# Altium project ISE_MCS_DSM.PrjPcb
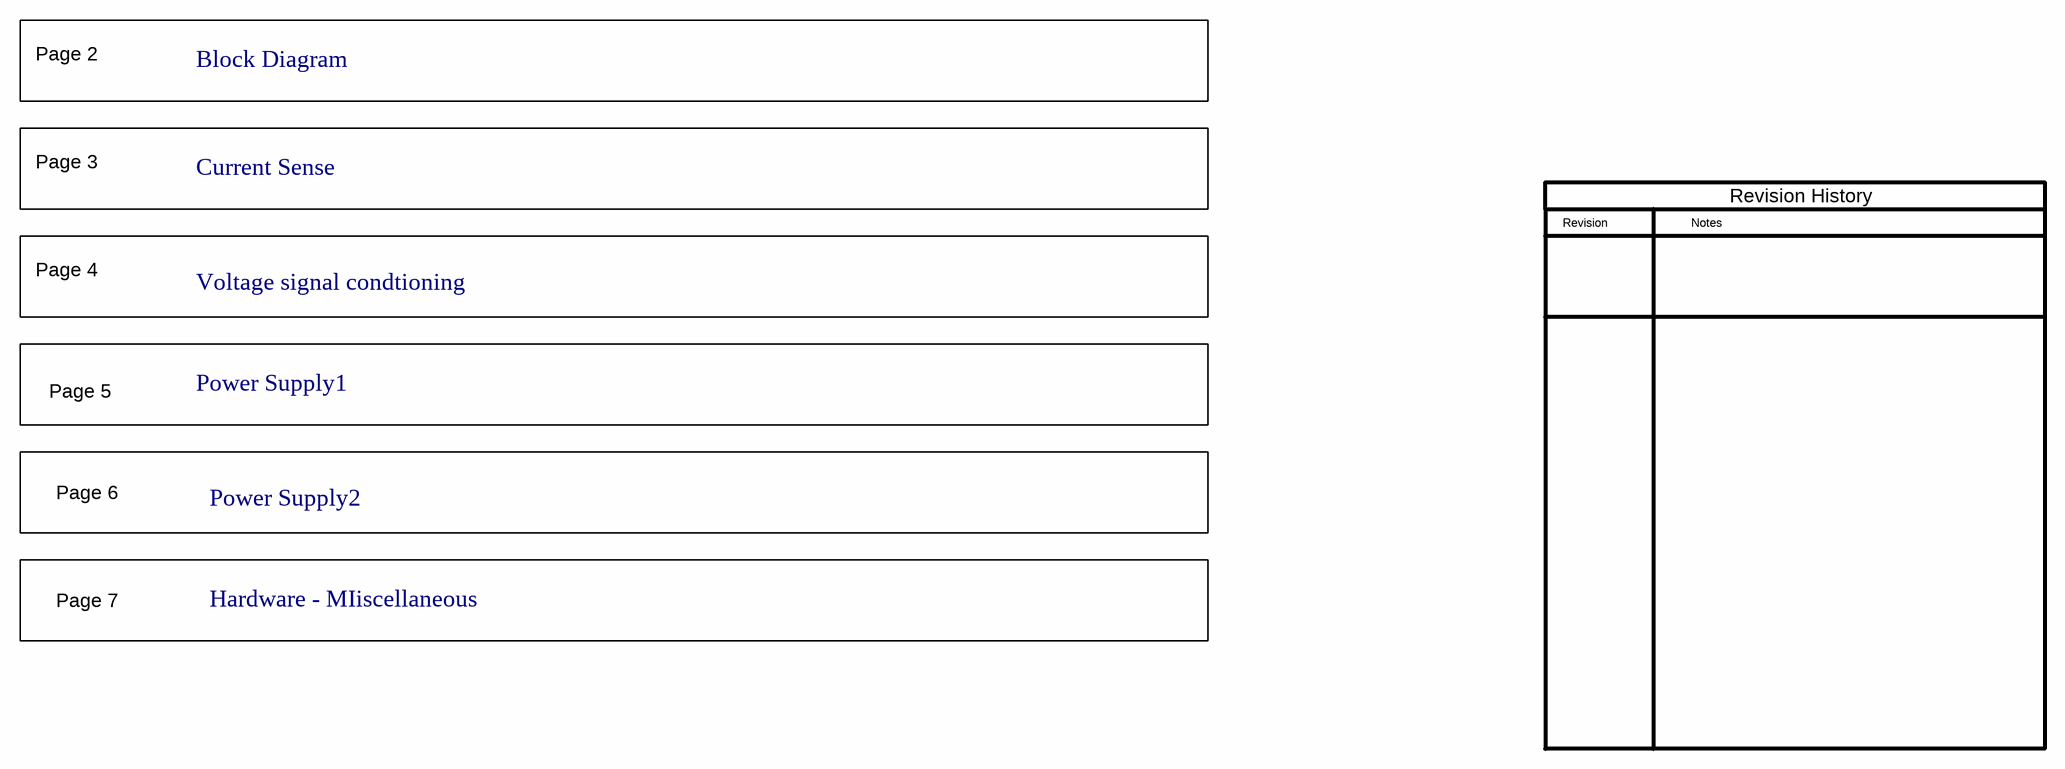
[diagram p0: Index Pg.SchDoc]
CopyrightYear: 2014; PCB_Layout: Vamsi T; PCB_Rev: E2; PRJ_Customer: Public Release; PRJ_Engineer: Narayanasamy Navaneeth; PRJ_Number: TIDA-00171; PRJ_Title: ISE_MCS_DSM_E2; SCH_Rev: E2; TechSupport: http://www.ti.com/support
7 sheets, 401 parts. Net scope: flat (ports and power ports of the same name join across sheets).
Board file: ISE_MCS_DSM_E2.PcbDoc
Sheets:
  Index Pg.SchDoc
  Block Diagram.SchDoc
  Current Sense.SchDoc
  Voltage signal conditioning.SchDoc
  Power supply 1.SchDoc
  Power supply 2.SchDoc
  Hardware.SchDoc

## Sheet Index Pg.SchDoc: Index Page
size 431 x 279 mm; Date: Not shown in title block; ApprovedBy: Not shown in title block; CheckedBy: Not shown in title block; Author: Not shown in title block; CompanyName: Not shown in title block; Engineer: Not shown in title block; Organization: Not shown in title block; Address1: Not shown in title block; Address2: Not shown in title block; Address3: Not shown in title block; Address4: Not shown in title block; DocumentNumber: 1; Revision: Use project parameter SCH_Rev; SheetNumber: 1; SheetTotal: 7; PageSetup: Record=PageOptions|CenterHorizontal=True|CenterVertical=True|PrintScale=1.00|XCorrection=1.00|YCorrection=1.00|PrintKind=0|BorderSize=5000000|LeftOffset=0|BottomOffset=0|Orientation=2|PaperLength=1000|PaperWidth=1000|Scale=100|PaperSource=15|PrintQuality=600|MediaType=1|DitherType=10|PaperKind=Letter|PrintScaleMode=1

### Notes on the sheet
- Page 2
- Block Diagram
- Page 3
- Current Sense
- Revision History
- Page 4
- Revision
- Notes
- Voltage signal condtioning
- Page 5
- Power Supply1
- Page 6
- Power Supply2
- Page 7
- Hardware - MIiscellaneous

## Sheet Block Diagram.SchDoc: Block Diagram
size 431 x 279 mm; Date: Not shown in title block; ApprovedBy: Not shown in title block; CheckedBy: Not shown in title block; Author: Not shown in title block; CompanyName: Not shown in title block; Engineer: Not shown in title block; Organization: Not shown in title block; Address1: Not shown in title block; Address2: Not shown in title block; Address3: Not shown in title block; Address4: Not shown in title block; DocumentNumber: 2; Revision: Use project parameter SCH_Rev; SheetNumber: 2; SheetTotal: 7; PageSetup: Record=PageOptions|CenterHorizontal=True|CenterVertical=True|PrintScale=1.00|XCorrection=1.00|YCorrection=1.00|PrintKind=0|BorderSize=5000000|LeftOffset=0|BottomOffset=0|Orientation=2|PaperLength=1000|PaperWidth=1000|Scale=100|PaperSource=15|PrintQuality=600|MediaType=1|DitherType=10|PaperKind=Letter|PrintScaleMode=1
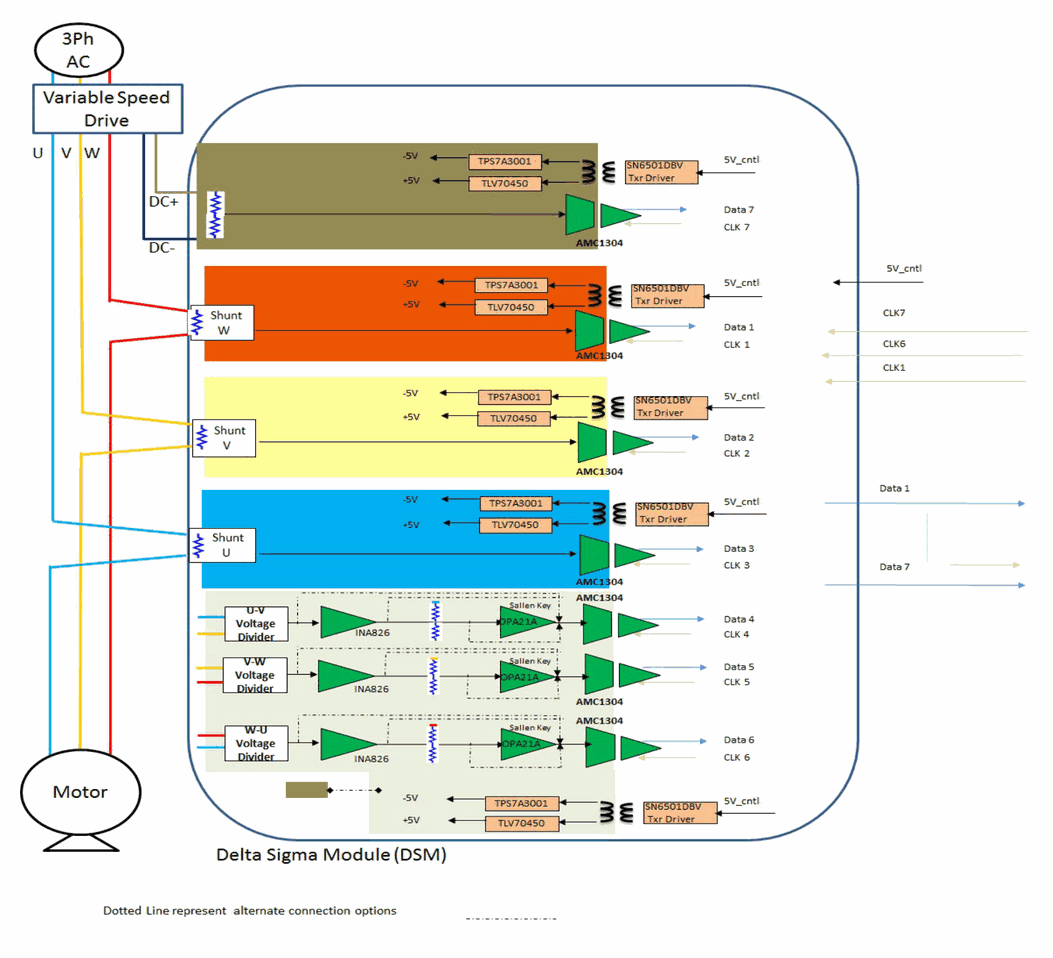
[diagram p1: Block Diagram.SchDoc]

## Sheet Current Sense.SchDoc: current Sense
size 431 x 279 mm; Date: Not shown in title block; ApprovedBy: Not shown in title block; CheckedBy: Not shown in title block; Author: Not shown in title block; CompanyName: Not shown in title block; Engineer: Not shown in title block; Organization: Not shown in title block; Address1: Not shown in title block; Address2: Not shown in title block; Address3: Not shown in title block; Address4: Not shown in title block; DocumentNumber: 3; Revision: Use project parameter SCH_Rev; SheetNumber: 3; SheetTotal: 7; PageSetup: Record=PageOptions¦CenterHorizontal=True¦CenterVertical=True¦PrintScale=1.00¦XCorrection=1.00¦YCorrection=1.00¦PrintKind=0¦BorderSize=5000000¦LeftOffset=0¦BottomOffset=0¦Orientation=2¦PaperLength=1000¦PaperWidth=1000¦Scale=100¦PaperSource=15¦PrintQuality=600¦MediaType=1¦DitherType=10¦PaperKind=Letter¦PrintScaleMode=1
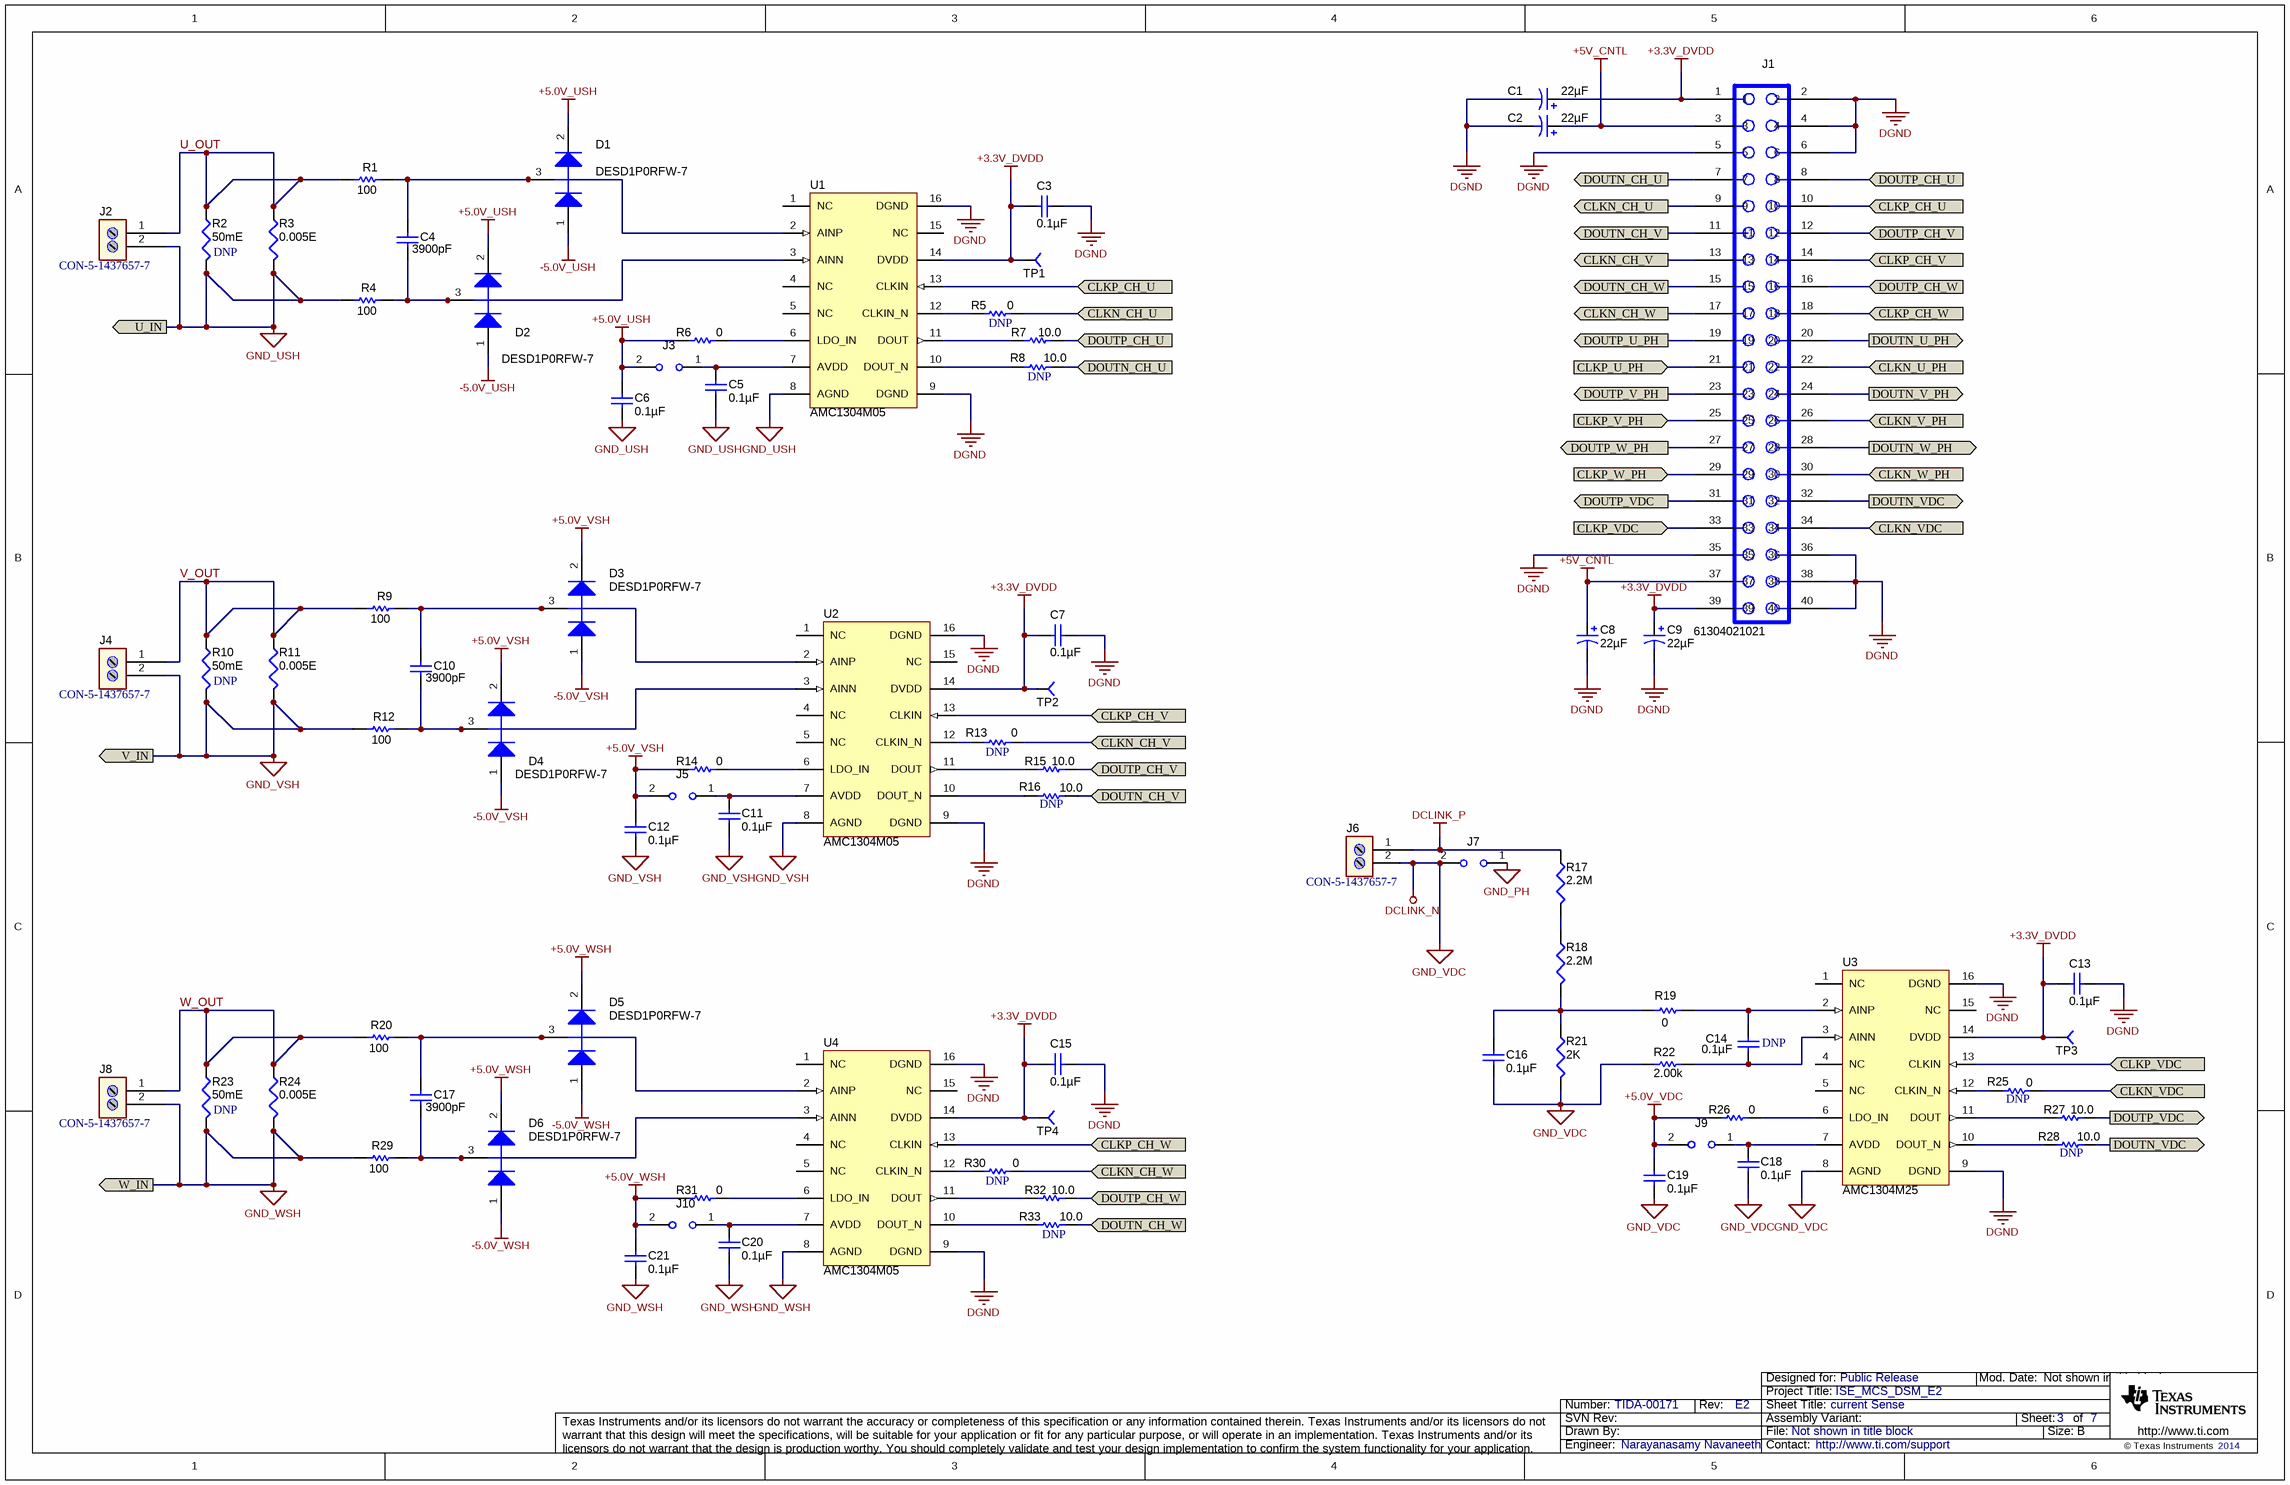
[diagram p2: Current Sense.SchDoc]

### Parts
C1  ValueDisplayed: 22µF  [SM_RADIAL_5MM]  (hidden comment: UUD1E220MCL1GS)
C2  ValueDisplayed: 22µF  [SM_RADIAL_5MM]  (hidden comment: UUD1E220MCL1GS)
C3  ValueDisplayed: 0.1µF  [0603]
C4  ValueDisplayed: 3900pF  [0603]  (hidden comment: C1608C0G1E392J)
C5  ValueDisplayed: 0.1µF  [0603]
C6  ValueDisplayed: 0.1µF  [0603]
C7  ValueDisplayed: 0.1µF  [0603]
C8  ValueDisplayed: 22µF  [SM_RADIAL_5MM]  (hidden comment: UUD1E220MCL1GS)
C9  ValueDisplayed: 22µF  [SM_RADIAL_5MM]  (hidden comment: UUD1E220MCL1GS)
C10  ValueDisplayed: 3900pF  [0603]  (hidden comment: C1608C0G1E392J)
C11  ValueDisplayed: 0.1µF  [0603]
C12  ValueDisplayed: 0.1µF  [0603]
C13  ValueDisplayed: 0.1µF  [0603]
C14  ValueDisplayed: 0.1µF  Not mounted: DNP  [0603]
C15  ValueDisplayed: 0.1µF  [0603]
C16  ValueDisplayed: 0.1µF  [0603]
C17  ValueDisplayed: 3900pF  [0603]  (hidden comment: C1608C0G1E392J)
C18  ValueDisplayed: 0.1µF  [0603]
C19  ValueDisplayed: 0.1µF  [0603]
C20  ValueDisplayed: 0.1µF  [0603]
C21  ValueDisplayed: 0.1µF  [0603]
D1  value DESD1P0RFW-7  [SOT-323]
D2  value DESD1P0RFW-7  [SOT-323]
D3  DESD1P0RFW-7  [SOT-323]
D4  DESD1P0RFW-7  [SOT-323]
D5  DESD1P0RFW-7  [SOT-323]
D6  DESD1P0RFW-7  [SOT-323]
J1  61304021021  [CONN_61304021021]
J2  CON-5-1437657-7  [5-1437657-7]
J3  (no value)  [HDR100_1X2]
J4  CON-5-1437657-7  [5-1437657-7]
J5  (no value)  [HDR100_1X2]
J6  CON-5-1437657-7  [5-1437657-7]
J7  (no value)  [HDR100_1X2]
J8  CON-5-1437657-7  [5-1437657-7]
J9  (no value)  [HDR100_1X2]
J10  (no value)  [HDR100_1X2]
R1  value 100  [0603]  (hidden comment: RC0603FR-07100RL)
R2  value 50mE  Not mounted: DNP  [R_TO-247]  (hidden comment: PBH-R050-F1-0.5)
R3  value 0.005E  [PWR4413D-R050F]  (hidden comment: OAR5R005FLF)
R4  value 100  [0603]  (hidden comment: RC0603FR-07100RL)
R5  value 0  Not mounted: DNP  [0603]
R6  value 0  [0603]
R7  value 10.0  [0603]
R8  value 10.0  Not mounted: DNP  [0603]
R9  value 100  [0603]  (hidden comment: RC0603FR-07100RL)
R10  value 50mE  Not mounted: DNP  [R_TO-247]  (hidden comment: PBH-R050-F1-0.5)
R11  value 0.005E  [PWR4413D-R050F]  (hidden comment: OAR5R005FLF)
R12  value 100  [0603]  (hidden comment: RC0603FR-07100RL)
R13  value 0  Not mounted: DNP  [0603]
R14  value 0  [0603]
R15  value 10.0  [0603]
R16  value 10.0  Not mounted: DNP  [0603]
R17  value 2.2M  [1210M]
R18  value 2.2M  [1210M]
R19  value 0  [0603]  (hidden comment: CRCW06030000Z0EA)
R20  value 100  [0603]  (hidden comment: RC0603FR-07100RL)
R21  value 2K  [1210M]
R22  value 2.00k  [0603]  (hidden comment: RT0603DRE072KL)
R23  value 50mE  Not mounted: DNP  [R_TO-247]  (hidden comment: PBH-R050-F1-0.5)
R24  value 0.005E  [PWR4413D-R050F]  (hidden comment: OAR5R005FLF)
R25  value 0  Not mounted: DNP  [0603]
R26  value 0  [0603]
R27  value 10.0  [0603]
R28  value 10.0  Not mounted: DNP  [0603]
R29  value 100  [0603]  (hidden comment: RC0603FR-07100RL)
R30  value 0  Not mounted: DNP  [0603]
R31  value 0  [0603]
R32  value 10.0  [0603]
R33  value 10.0  Not mounted: DNP  [0603]
TP1  (no value)  [TP-040_RND]
TP2  (no value)  [TP-040_RND]
TP3  (no value)  [TP-040_RND]
TP4  (no value)  [TP-040_RND]
U1  AMC1304M05  [DW0016A_N]
U2  AMC1304M05  [DW0016A_N]
U3  AMC1304M25  [DW0016A_N]
U4  AMC1304M05  [DW0016A_N]

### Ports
CLKN_CH_U, CLKN_CH_V, CLKN_CH_W, CLKN_U_PH (in), CLKN_V_PH (in), CLKN_VDC (in), CLKN_W_PH (in), CLKP_CH_U, CLKP_CH_V, CLKP_CH_W, CLKP_U_PH (in), CLKP_V_PH (in), CLKP_VDC (in), CLKP_W_PH (in), DOUTN_CH_U, DOUTN_CH_V, DOUTN_CH_W, DOUTN_U_PH (out), DOUTN_V_PH (out), DOUTN_VDC (out), DOUTN_W_PH (out), DOUTP_CH_U, DOUTP_CH_V, DOUTP_CH_W, DOUTP_U_PH (out), DOUTP_V_PH (out), DOUTP_VDC (out), DOUTP_W_PH (out), U_IN (out), V_IN (out), W_IN (out)

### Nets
+3.3V_DVDD: C1.1(+) C3.2 C7.2 C9.1(+) C13.2 C15.2 J1.1 J1.39 TP1.1 TP2.1 TP3.1 TP4.1 U1.14(DVDD) U2.14(DVDD) U3.14(DVDD) U4.14(DVDD)
+5.0V_USH: C6.1 D1.2(K) D2.2(K) J3.2 R6.1
+5.0V_VDC: C19.1 J9.2 R26.1
+5.0V_VSH: C12.1 D3.2(K) D4.2(K) J5.2 R14.1
+5.0V_WSH: C21.1 D5.2(K) D6.2(K) J10.2 R31.1
+5V_CNTL: C2.1(+) C8.1(+) J1.3 J1.37
-5.0V_USH: D1.1(A) D2.1(A)
-5.0V_VSH: D3.1(A) D4.1(A)
-5.0V_WSH: D5.1(A) D6.1(A)
DCLINK_N: C16.1 C18.2 C19.2 J6.2 J7.2 R21.2 R22.1 U3.8(AGND)  [also labelled GND_VDC]
DCLINK_P: J6.1 R17.1
DGND: C1.2(-) C2.2(-) C3.1 C7.1 C8.2(-) C9.2(-) C13.1 C15.1 J1.2 J1.4 J1.5 J1.6 J1.35 J1.36 J1.38 J1.40 U1.9(DGND) U1.16(DGND) U2.9(DGND) U2.16(DGND) U3.9(DGND) U3.16(DGND) U4.9(DGND) U4.16(DGND)
GND_PH: J7.1
GND_USH: C5.2 C6.2 J2.2 R2.2 R3.2 R4.1 U1.8(AGND) ; port U_IN
GND_VSH: C11.2 C12.2 J4.2 R10.2 R11.2 R12.1 U2.8(AGND) ; port V_IN
GND_WSH: C20.2 C21.2 J8.2 R23.2 R24.2 R29.1 U4.8(AGND) ; port W_IN
CLKN_CH_U: J1.9 R5.2 ; port CLKN_CH_U
CLKN_CH_V: J1.13 R13.2 ; port CLKN_CH_V
CLKN_CH_W: J1.17 R30.2 ; port CLKN_CH_W
CLKN_U_PH: J1.22 ; port CLKN_U_PH
CLKN_V_PH: J1.26 ; port CLKN_V_PH
CLKN_VDC: J1.34 R25.2 ; port CLKN_VDC
CLKN_W_PH: J1.30 ; port CLKN_W_PH
CLKP_CH_U: J1.10 U1.13(CLKIN) ; port CLKP_CH_U
CLKP_CH_V: J1.14 U2.13(CLKIN) ; port CLKP_CH_V
CLKP_CH_W: J1.18 U4.13(CLKIN) ; port CLKP_CH_W
CLKP_U_PH: J1.21 ; port CLKP_U_PH
CLKP_V_PH: J1.25 ; port CLKP_V_PH
CLKP_VDC: J1.33 U3.13(CLKIN) ; port CLKP_VDC
CLKP_W_PH: J1.29 ; port CLKP_W_PH
DOUTN_CH_U: J1.7 R8.2 ; port DOUTN_CH_U
DOUTN_CH_V: J1.11 R16.2 ; port DOUTN_CH_V
DOUTN_CH_W: J1.15 R33.2 ; port DOUTN_CH_W
DOUTN_U_PH: J1.20 ; port DOUTN_U_PH
DOUTN_V_PH: J1.24 ; port DOUTN_V_PH
DOUTN_VDC: J1.32 R28.2 ; port DOUTN_VDC
DOUTN_W_PH: J1.28 ; port DOUTN_W_PH
DOUTP_CH_U: J1.8 R7.2 ; port DOUTP_CH_U
DOUTP_CH_V: J1.12 R15.2 ; port DOUTP_CH_V
DOUTP_CH_W: J1.16 R32.2 ; port DOUTP_CH_W
DOUTP_U_PH: J1.19 ; port DOUTP_U_PH
DOUTP_V_PH: J1.23 ; port DOUTP_V_PH
DOUTP_VDC: J1.31 R27.2 ; port DOUTP_VDC
DOUTP_W_PH: J1.27 ; port DOUTP_W_PH
U_OUT: J2.1 R1.1 R2.1 R3.1
V_OUT: J4.1 R9.1 R10.1 R11.1
W_OUT: J8.1 R20.1 R23.1 R24.1
NetC4_1: C4.1 D1.3(C) R1.2 U1.2(AINP)
NetC4_2: C4.2 D2.3(C) R4.2 U1.3(AINN)
NetC5_1: C5.1 J3.1 U1.7(AVDD)
NetC10_1: C10.1 D3.3(C) R9.2 U2.2(AINP)
NetC10_2: C10.2 D4.3(C) R12.2 U2.3(AINN)
NetC11_1: C11.1 J5.1 U2.7(AVDD)
NetC14_1: C14.1 R19.2 U3.2(AINP)
NetC14_2: C14.2 R22.2 U3.3(AINN)
NetC16_2: C16.2 R18.2 R19.1 R21.1
NetC17_1: C17.1 D5.3(C) R20.2 U4.2(AINP)
NetC17_2: C17.2 D6.3(C) R29.2 U4.3(AINN)
NetC18_1: C18.1 J9.1 U3.7(AVDD)
NetC20_1: C20.1 J10.1 U4.7(AVDD)
NetR5_1: R5.1 U1.12(CLKIN_N)
NetR6_2: R6.2 U1.6(LDO_IN)
NetR7_1: R7.1 U1.11(DOUT)
NetR8_1: R8.1 U1.10(DOUT_N)
NetR13_1: R13.1 U2.12(CLKIN_N)
NetR14_2: R14.2 U2.6(LDO_IN)
NetR15_1: R15.1 U2.11(DOUT)
NetR16_1: R16.1 U2.10(DOUT_N)
NetR17_2: R17.2 R18.1
NetR25_1: R25.1 U3.12(CLKIN_N)
NetR26_2: R26.2 U3.6(LDO_IN)
NetR27_1: R27.1 U3.11(DOUT)
NetR28_1: R28.1 U3.10(DOUT_N)
NetR30_1: R30.1 U4.12(CLKIN_N)
NetR31_2: R31.2 U4.6(LDO_IN)
NetR32_1: R32.1 U4.11(DOUT)
NetR33_1: R33.1 U4.10(DOUT_N)

Not connected (* = marked no-connect by the designer): U1 1(NC) 4(NC) 5(NC) 15(NC); U2 1(NC) 4(NC) 5(NC) 15(NC); U3 1(NC) 4(NC) 5(NC) 15(NC); U4 1(NC) 4(NC) 5(NC) 15(NC)

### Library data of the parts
C1 C2 C8 C9 = UUD1E220MCL1GS: CAP, AL, 22uF, 25V, +/-20%, 0.76 ohm, SMD; Manufacturer: Nichicon; Polarized: Y; CompType: Capacitor; U/M: EA; Cap_F: 0.000022; Tolerance_%: 20; VDC_V: 25; ESR_Ohm: 0.76; IRMS_A: 0.15; TaMin_C: -55; TaMax_C: 105; Cap_Case: 5x5.8
C3 C7 C13 C15 = 06033C104JAT2A: CAP, CERM, 0.1uF, 25V, +/-5%, X7R, 0603; Manufacturer: AVX; Polarized: N; CompType: Capacitor; U/M: EA; Cap_F: 0.0000001; Tolerance_%: 5; ESR_Ohm: 0.05; Value1: 0.05 ohm; VDC_V: 25; TaMin_C: -55; TaMax_C: 125
C4 C10 C17 = C1608C0G1E392J: CAP, CERM, 3900pF, 25V, +/-5%, C0G/NP0, 0603; Manufacturer: TDK; Polarized: N; CompType: Capacitor; U/M: EA; Cap_F: 0.0000000039; Tolerance_%: 5; Value1: Unknown; VDC_V: 25; TaMin_C: -55; TaMax_C: 125
C5 C6 C11 C12 C14 C16 C18-C21 = C0603C104K5RACTU: CAP, CERM, 0.1uF, 50V, +/-10%, X7R, 0603; Manufacturer: Kemet; Polarized: N; CompType: Capacitor; U/M: EA; Cap_F: 0.0000001; Tolerance_%: 10; Value1: Unknown; VDC_V: 50; TaMin_C: -55; TaMax_C: 125
D1 D2 = BAV99WT1G: Diode, P-N, 70V, 0.2A, SOT-323; Manufacturer: Diodes Inc
D3-D6 = BAV99WT1G: Diode, P-N, 70V, 0.2A, SOT-323; Manufacturer: Diodes Inc; Value: DNP
J1 = CONN_61304021021: Connector, Right Angle 2x20 pin, 100mil spacing; Manufacturer: WURTH ELEKTRONIK; area: 1.262.250
J2 J4 J6 J8 = CON-5-1437657-7: Terminal Block, 4x1, 2.54mm, TH; Manufacturer: On Shore Technology Inc; PartNumber: OSTVN02A150; SymbolCreator: x0120606
J3 J5 J7 J9 J10 = JUMPER_2X100MIL: Header, Male 2-pin, 100mil spacing,; Manufacturer: Sullins; PartNumber: PEC02SAAN; area: 20000; Value: PEC02SAAN
R1 R4 R9 R12 R20 R29 = RC0603FR-07100RL: RES, 100 ohm, 1%, 0.1W, 0603; Manufacturer: Yageo America; CompType: Resistor; Value_Code: 100R; Tolerance_%: 1; Power_W: 0.1; VDC_V: 150; TempCo: 200 ppm/C; EIA_Code: E96; U/M: EA
R2 R10 R23 = PBH-R050-F1-0.5: RES 50mOHM 3W .5% TO-247 TH; Manufacturer: ISOTEK; CompType: Resistor
R3 R11 R24 = RES_PWR4413DR050F: RES METAL .005 OHM 5W 1% RADIAL; Manufacturer: TT Electronics/IRC; CompType: Resistor
R5 R6 R13 R14 R19 R25 R26 R30 R31 = CRCW06030000Z0EA: RES, 0 ohm, 5%, 0.1W, 0603; Manufacturer: Vishay-Dale; CompType: Resistor; Value_Code: 0000; Tolerance_%: 5; Power_W: 0.1; VDC_V: 75; TempCo: 200 ppm/C; EIA_Code: E24; U/M: EA
R7 R8 R15 R16 R27 R28 R32 R33 = CRCW060310R0FKEA: RES, 10.0 ohm, 1%, 0.1W, 0603; Manufacturer: Vishay-Dale; CompType: Resistor; Res_ohm: 10; Value_Code: 10R0; Tolerance_%: 1; Power_W: 0.1; VDC_V: 75; TempCo: 100 ppm/C; EIA_Code: E96; U/M: EA
R17 R18 = RES_KTR25JZPF2204: RES 2.2M OHM 1/3W 1% 1210; Manufacturer: Rohm Semiconductor; CompType: Resistor
R21 = RES_KTR25JZPF2001: RES 2K OHM 1/3W 1% 1210; Manufacturer: Rohm Semiconductor; CompType: Resistor
R22 = RT0603DRE072KL: RES, 2.00k ohm, 0.5%, 0.1W, 0603; Manufacturer: Yageo America; CompType: Resistor; Res_ohm: 2000; Value_Code: 2k00; Tolerance_%: 0.5; Power_W: 0.1; VDC_V: 75; TempCo: 50 ppm/C; EIA_Code: E192; U/M: EA
TP1-TP4 = TP-040_RND: Test Point, O.040 Hole; Manufacturer: STD; Value: STD
U1-U4 = AMC1304L25: 20 MHz, Isolated Delta-Sigma Modulator, LVDS interface:; Alternate Manufacturer: None; Manufacturer: Texas Instruments; SymbolCreator: x0120606; CompType: IC

## Sheet Voltage signal conditioning.SchDoc: Voltage Signal Conditioning
size 431 x 279 mm; Date: Not shown in title block; ApprovedBy: Not shown in title block; CheckedBy: Not shown in title block; Author: Not shown in title block; CompanyName: Not shown in title block; Engineer: Not shown in title block; Organization: Not shown in title block; Address1: Not shown in title block; Address2: Not shown in title block; Address3: Not shown in title block; Address4: Not shown in title block; DocumentNumber: 4; Revision: Use project parameter SCH_Rev; SheetNumber: 4; SheetTotal: 7; PageSetup: Record=PageOptions|CenterHorizontal=True|CenterVertical=True|PrintScale=1.00|XCorrection=1.00|YCorrection=1.00|PrintKind=0|BorderSize=5000000|LeftOffset=0|BottomOffset=0|Orientation=2|PaperLength=1000|PaperWidth=1000|Scale=100|PaperSource=15|PrintQuality=600|MediaType=1|DitherType=10|PaperKind=Letter|PrintScaleMode=1
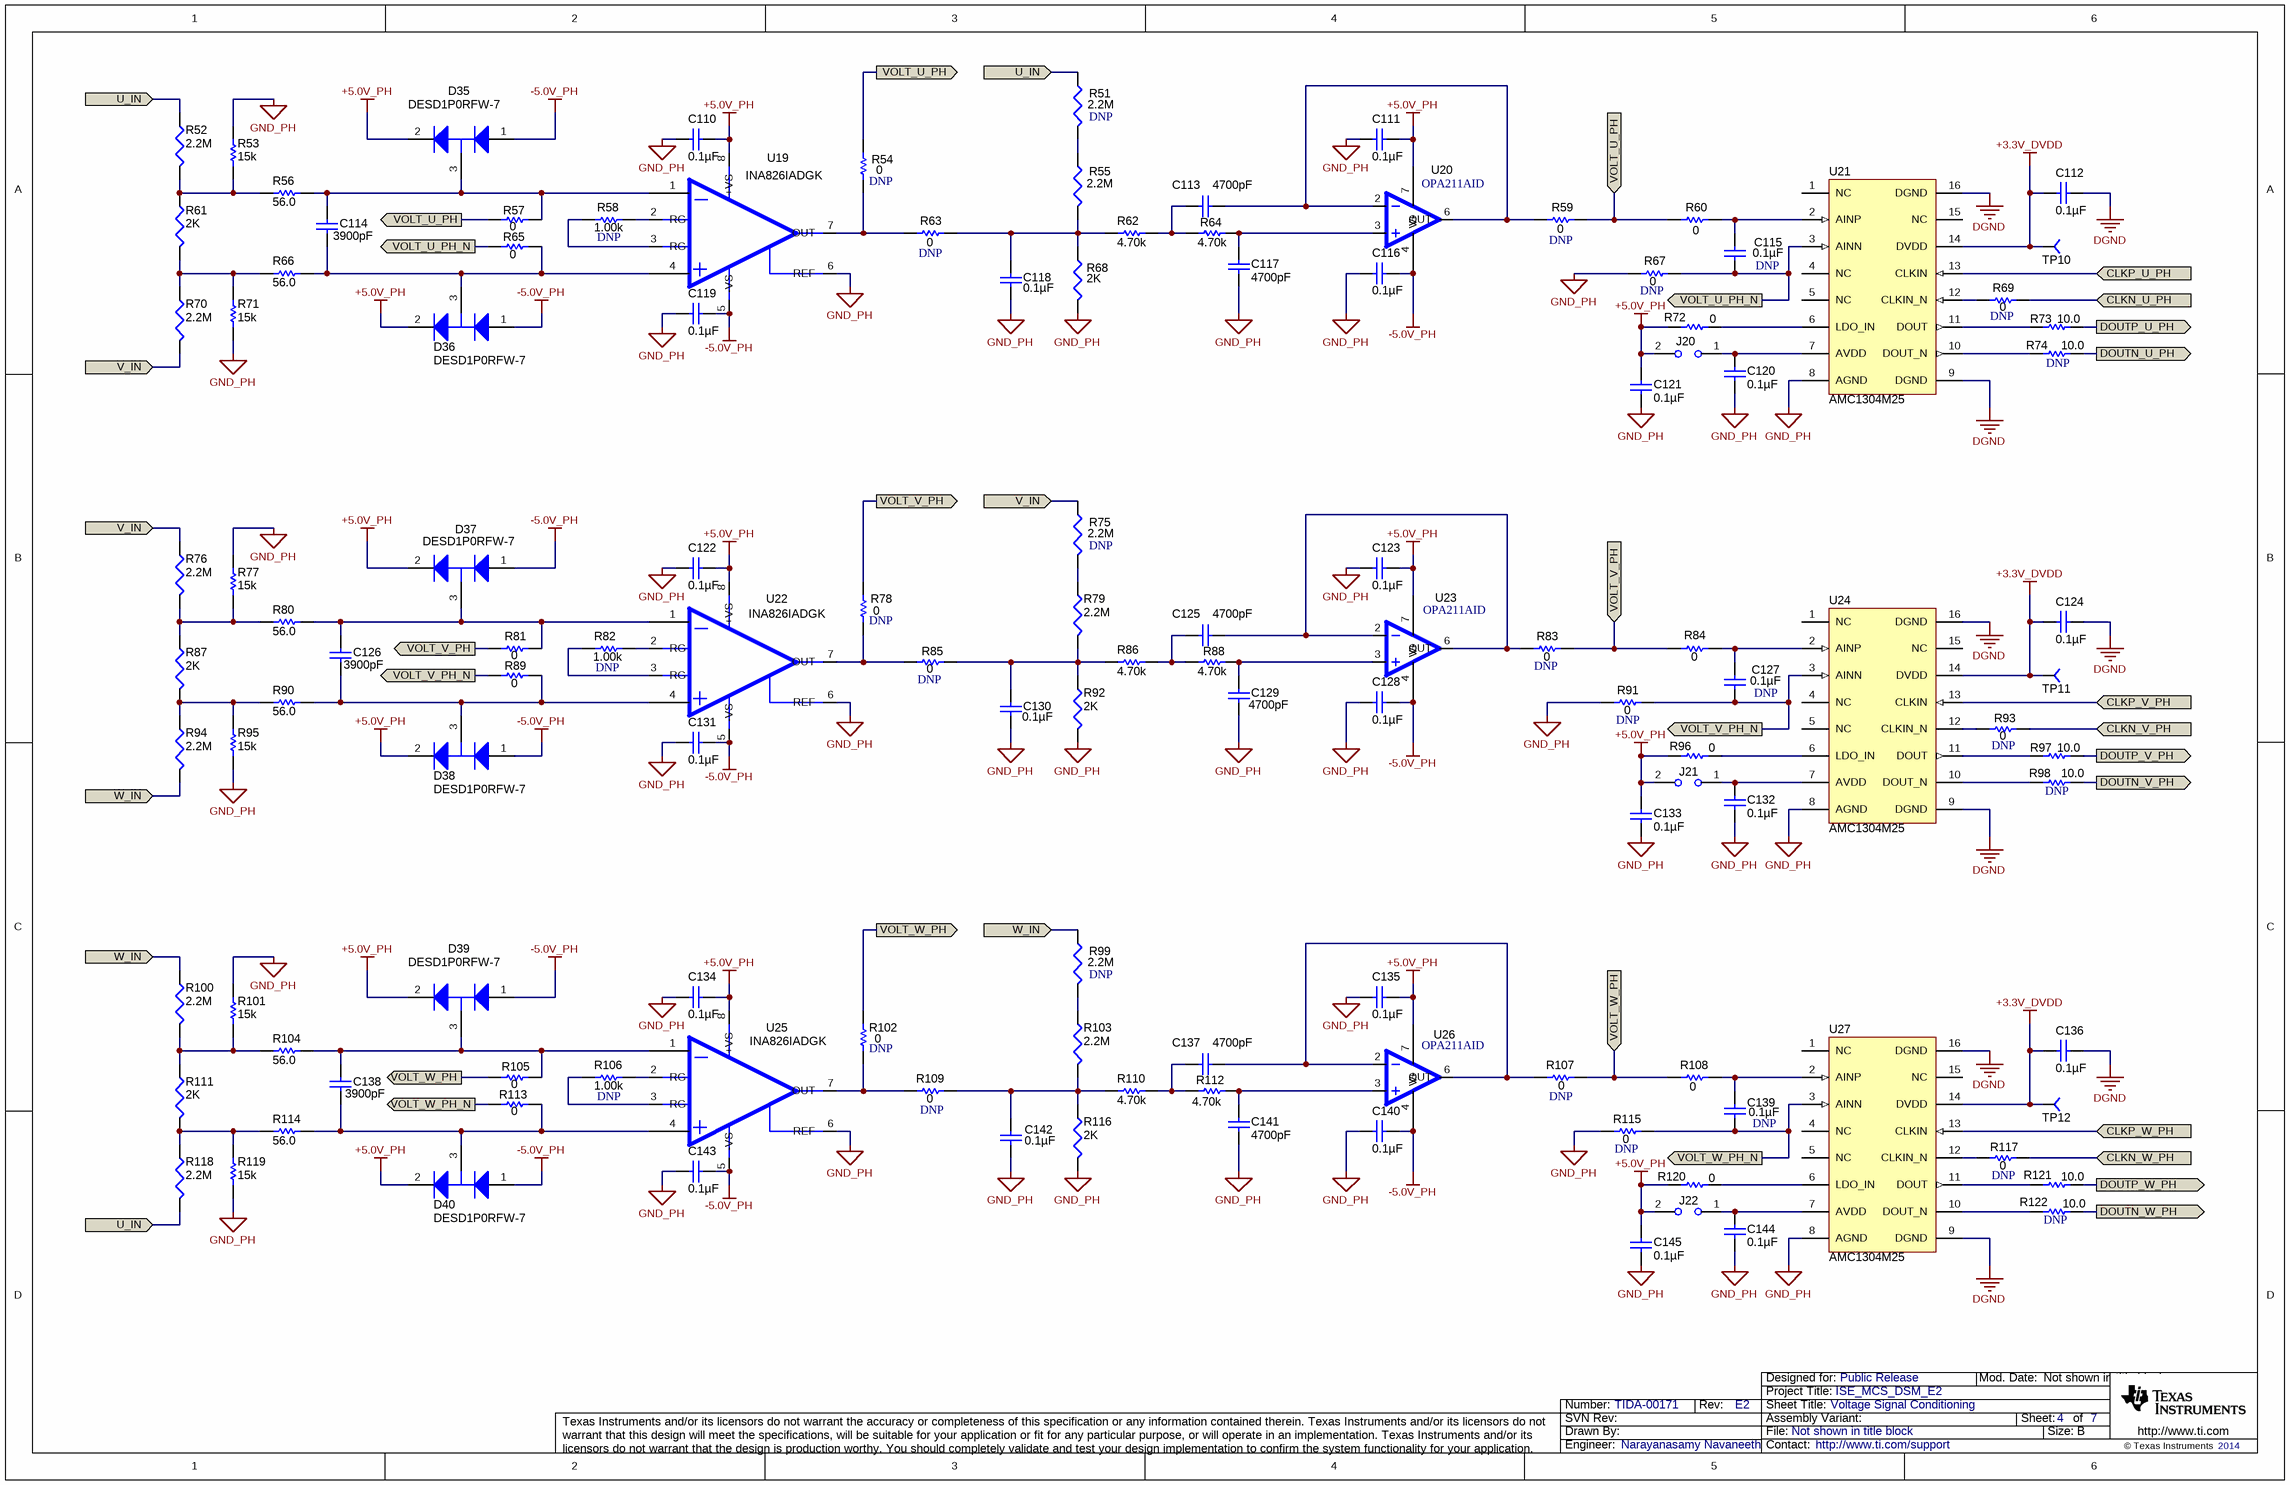
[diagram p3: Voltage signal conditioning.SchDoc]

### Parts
C110  ValueDisplayed: 0.1µF  [0603]
C111  ValueDisplayed: 0.1µF  [0603]
C112  ValueDisplayed: 0.1µF  [0603]
C113  ValueDisplayed: 4700pF  [0603]
C114  ValueDisplayed: 3900pF  [0603]  (hidden comment: C1608C0G1E392J)
C115  ValueDisplayed: 0.1µF  Not mounted: DNP  [0603]
C116  ValueDisplayed: 0.1µF  [0603]
C117  ValueDisplayed: 4700pF  [0603]
C118  ValueDisplayed: 0.1µF  [0603]
C119  ValueDisplayed: 0.1µF  [0603]
C120  ValueDisplayed: 0.1µF  [0603]
C121  ValueDisplayed: 0.1µF  [0603]
C122  ValueDisplayed: 0.1µF  [0603]
C123  ValueDisplayed: 0.1µF  [0603]
C124  ValueDisplayed: 0.1µF  [0603]
C125  ValueDisplayed: 4700pF  [0603]
C126  ValueDisplayed: 3900pF  [0603]  (hidden comment: C1608C0G1E392J)
C127  ValueDisplayed: 0.1µF  Not mounted: DNP  [0603]
C128  ValueDisplayed: 0.1µF  [0603]
C129  ValueDisplayed: 4700pF  [0603]
C130  ValueDisplayed: 0.1µF  [0603]
C131  ValueDisplayed: 0.1µF  [0603]
C132  ValueDisplayed: 0.1µF  [0603]
C133  ValueDisplayed: 0.1µF  [0603]
C134  ValueDisplayed: 0.1µF  [0603]
C135  ValueDisplayed: 0.1µF  [0603]
C136  ValueDisplayed: 0.1µF  [0603]
C137  ValueDisplayed: 4700pF  [0603]
C138  ValueDisplayed: 3900pF  [0603]  (hidden comment: C1608C0G1E392J)
C139  ValueDisplayed: 0.1µF  Not mounted: DNP  [0603]
C140  ValueDisplayed: 0.1µF  [0603]
C141  ValueDisplayed: 4700pF  [0603]
C142  ValueDisplayed: 0.1µF  [0603]
C143  ValueDisplayed: 0.1µF  [0603]
C144  ValueDisplayed: 0.1µF  [0603]
C145  ValueDisplayed: 0.1µF  [0603]
D35  DESD1P0RFW-7  [SOT-323]
D36  DESD1P0RFW-7  [SOT-323]
D37  DESD1P0RFW-7  [SOT-323]
D38  DESD1P0RFW-7  [SOT-323]
D39  DESD1P0RFW-7  [SOT-323]
D40  DESD1P0RFW-7  [SOT-323]
J20  (no value)  [HDR100_1X2]
J21  (no value)  [HDR100_1X2]
J22  (no value)  [HDR100_1X2]
R51  value 2.2M  Not mounted: DNP  [1210M]
R52  value 2.2M  [1210M]
R53  value 15k  [0603]
R54  value 0  Not mounted: DNP  [0603]
R55  value 2.2M  [1210M]
R56  value 56.0  [0603]  (hidden comment: RC0603FR-0756RL)
R57  value 0  [0603]
R58  value 1.00k  Not mounted: DNP  [0603]
R59  value 0  Not mounted: DNP  [0603]
R60  value 0  [0603]  (hidden comment: CRCW06030000Z0EA)
R61  value 2K  [1210M]
R62  value 4.70k  [0603]
R63  value 0  Not mounted: DNP  [0603]
R64  value 4.70k  [0603]
R65  value 0  [0603]
R66  value 56.0  [0603]  (hidden comment: RC0603FR-0756RL)
R67  value 0  Not mounted: DNP  [0603]
R68  value 2K  [1210M]
R69  value 0  Not mounted: DNP  [0603]
R70  value 2.2M  [1210M]
R71  value 15k  [0603]
R72  value 0  [0603]
R73  value 10.0  [0603]
R74  value 10.0  Not mounted: DNP  [0603]
R75  value 2.2M  Not mounted: DNP  [1210M]
R76  value 2.2M  [1210M]
R77  value 15k  [0603]
R78  value 0  Not mounted: DNP  [0603]
R79  value 2.2M  [1210M]
R80  value 56.0  [0603]  (hidden comment: RC0603FR-0756RL)
R81  value 0  [0603]
R82  value 1.00k  Not mounted: DNP  [0603]
R83  value 0  Not mounted: DNP  [0603]
R84  value 0  [0603]  (hidden comment: CRCW06030000Z0EA)
R85  value 0  Not mounted: DNP  [0603]
R86  value 4.70k  [0603]
R87  value 2K  [1210M]
R88  value 4.70k  [0603]
R89  value 0  [0603]
R90  value 56.0  [0603]  (hidden comment: RC0603FR-0756RL)
R91  value 0  Not mounted: DNP  [0603]
R92  value 2K  [1210M]
R93  value 0  Not mounted: DNP  [0603]
R94  value 2.2M  [1210M]
R95  value 15k  [0603]
R96  value 0  [0603]
R97  value 10.0  [0603]
R98  value 10.0  Not mounted: DNP  [0603]
R99  value 2.2M  Not mounted: DNP  [1210M]
R100  value 2.2M  [1210M]
R101  value 15k  [0603]
R102  value 0  Not mounted: DNP  [0603]
R103  value 2.2M  [1210M]
R104  value 56.0  [0603]  (hidden comment: RC0603FR-0756RL)
R105  value 0  [0603]
R106  value 1.00k  Not mounted: DNP  [0603]
R107  value 0  Not mounted: DNP  [0603]
R108  value 0  [0603]  (hidden comment: CRCW06030000Z0EA)
R109  value 0  Not mounted: DNP  [0603]
R110  value 4.70k  [0603]
R111  value 2K  [1210M]
R112  value 4.70k  [0603]
R113  value 0  [0603]
R114  value 56.0  [0603]  (hidden comment: RC0603FR-0756RL)
R115  value 0  Not mounted: DNP  [0603]
R116  value 2K  [1210M]
R117  value 0  Not mounted: DNP  [0603]
R118  value 2.2M  [1210M]
R119  value 15k  [0603]
R120  value 0  [0603]
R121  value 10.0  [0603]
R122  value 10.0  Not mounted: DNP  [0603]
TP10  (no value)  [TP-040_RND]
TP11  (no value)  [TP-040_RND]
TP12  (no value)  [TP-040_RND]
U19  INA826IADGK  [DGK8]
U20  OPA211AID  [SO8]
U21  AMC1304M25  [DW0016A_N]
U22  INA826IADGK  [DGK8]
U23  OPA211AID  [SO8]
U24  AMC1304M25  [DW0016A_N]
U25  INA826IADGK  [DGK8]
U26  OPA211AID  [SO8]
U27  AMC1304M25  [DW0016A_N]

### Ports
CLKN_U_PH (in), CLKN_V_PH (in), CLKN_W_PH (in), CLKP_U_PH (in), CLKP_V_PH (in), CLKP_W_PH (in), DOUTN_U_PH (out), DOUTN_V_PH (out), DOUTN_W_PH (out), DOUTP_U_PH (out), DOUTP_V_PH (out), DOUTP_W_PH (out), U_IN, V_IN, VOLT_U_PH (in), VOLT_U_PH (out), VOLT_U_PH_N (out), VOLT_V_PH (in), VOLT_V_PH (out), VOLT_V_PH_N (out), VOLT_W_PH (in), VOLT_W_PH (out), VOLT_W_PH_N (out), W_IN

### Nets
+3.3V_DVDD: C112.2 C124.2 C136.2 TP10.1 TP11.1 TP12.1 U21.14(DVDD) U24.14(DVDD) U27.14(DVDD)
+5.0V_PH: C110.2 C111.2 C121.1 C122.2 C123.2 C133.1 C134.2 C135.2 C145.1 D35.2(K) D36.2(K) D37.2(K) D38.2(K) D39.2(K) D40.2(K) J20.2 J21.2 J22.2 R72.1 R96.1 R120.1 U19.8(+VS) U20.7(V+) U22.8(+VS) U23.7(V+) U25.8(+VS) U26.7(V+)
-5.0V_PH: C116.2 C119.2 C128.2 C131.2 C140.2 C143.2 D35.1(A) D36.1(A) D37.1(A) D38.1(A) D39.1(A) D40.1(A) U19.5(-VS) U20.4(V-) U22.5(-VS) U23.4(V-) U25.5(-VS) U26.4(V-)
DGND: C112.1 C124.1 C136.1 U21.9(DGND) U21.16(DGND) U24.9(DGND) U24.16(DGND) U27.9(DGND) U27.16(DGND)
GND_PH: C110.1 C111.1 C116.1 C117.2 C118.1 C119.1 C120.2 C121.2 C122.1 C123.1 C128.1 C129.2 C130.1 C131.1 C132.2 C133.2 C134.1 C135.1 C140.1 C141.2 C142.1 C143.1 C144.2 C145.2 R53.2 R67.2 R68.2 R71.1 R77.2 R91.2 R92.2 R95.1 R101.2 R115.2 R116.2 R119.1 U19.6(REF) U21.8(AGND) U22.6(REF) U24.8(AGND) U25.6(REF) U27.8(AGND)
GND_USH: R51.1 R52.1 R118.2 ; port U_IN
GND_VSH: R70.2 R75.1 R76.1 ; port V_IN
GND_WSH: R94.2 R99.1 R100.1 ; port W_IN
CLKN_U_PH: R69.2 ; port CLKN_U_PH
CLKN_V_PH: R93.2 ; port CLKN_V_PH
CLKN_W_PH: R117.2 ; port CLKN_W_PH
CLKP_U_PH: U21.13(CLKIN) ; port CLKP_U_PH
CLKP_V_PH: U24.13(CLKIN) ; port CLKP_V_PH
CLKP_W_PH: U27.13(CLKIN) ; port CLKP_W_PH
DOUTN_U_PH: R74.2 ; port DOUTN_U_PH
DOUTN_V_PH: R98.2 ; port DOUTN_V_PH
DOUTN_W_PH: R122.2 ; port DOUTN_W_PH
DOUTP_U_PH: R73.2 ; port DOUTP_U_PH
DOUTP_V_PH: R97.2 ; port DOUTP_V_PH
DOUTP_W_PH: R121.2 ; port DOUTP_W_PH
VOLT_U_PH: R54.2 R57.2 R59.2 R60.1 ; port VOLT_U_PH
VOLT_U_PH_N: C115.2 R65.2 R67.1 U21.3(AINN) ; port VOLT_U_PH_N
VOLT_V_PH: R78.2 R81.2 R83.2 R84.1 ; port VOLT_V_PH
VOLT_V_PH_N: C127.2 R89.2 R91.1 U24.3(AINN) ; port VOLT_V_PH_N
VOLT_W_PH: R102.2 R105.2 R107.2 R108.1 ; port VOLT_W_PH
VOLT_W_PH_N: C139.2 R113.2 R115.1 U27.3(AINN) ; port VOLT_W_PH_N
NetC113_1: C113.1 R62.2 R64.1
NetC113_2: C113.2 R59.1 U20.2 U20.6(OUT)
NetC114_1: C114.1 D35.3(C) R56.2 R57.1 U19.1
NetC114_2: C114.2 D36.3(C) R65.1 R66.2 U19.4
NetC115_1: C115.1 R60.2 U21.2(AINP)
NetC117_1: C117.1 R64.2 U20.3
NetC118_2: C118.2 R55.2 R62.1 R63.2 R68.1
NetC120_1: C120.1 J20.1 U21.7(AVDD)
NetC125_1: C125.1 R86.2 R88.1
NetC125_2: C125.2 R83.1 U23.2 U23.6(OUT)
NetC126_1: C126.1 D37.3(C) R80.2 R81.1 U22.1
NetC126_2: C126.2 D38.3(C) R89.1 R90.2 U22.4
NetC127_1: C127.1 R84.2 U24.2(AINP)
NetC129_1: C129.1 R88.2 U23.3
NetC130_2: C130.2 R79.2 R85.2 R86.1 R92.1
NetC132_1: C132.1 J21.1 U24.7(AVDD)
NetC137_1: C137.1 R110.2 R112.1
NetC137_2: C137.2 R107.1 U26.2 U26.6(OUT)
NetC138_1: C138.1 D39.3(C) R104.2 R105.1 U25.1
NetC138_2: C138.2 D40.3(C) R113.1 R114.2 U25.4
NetC139_1: C139.1 R108.2 U27.2(AINP)
NetC141_1: C141.1 R112.2 U26.3
NetC142_2: C142.2 R103.2 R109.2 R110.1 R116.1
NetC144_1: C144.1 J22.1 U27.7(AVDD)
NetR51_2: R51.2 R55.1
NetR52_2: R52.2 R53.1 R56.1 R61.1
NetR54_1: R54.1 R63.1 U19.7(OUT)
NetR58_1: R58.1 U19.3(RG)
NetR58_2: R58.2 U19.2(RG)
NetR61_2: R61.2 R66.1 R70.1 R71.2
NetR69_1: R69.1 U21.12(CLKIN_N)
NetR72_2: R72.2 U21.6(LDO_IN)
NetR73_1: R73.1 U21.11(DOUT)
NetR74_1: R74.1 U21.10(DOUT_N)
NetR75_2: R75.2 R79.1
NetR76_2: R76.2 R77.1 R80.1 R87.1
NetR78_1: R78.1 R85.1 U22.7(OUT)
NetR82_1: R82.1 U22.3(RG)
NetR82_2: R82.2 U22.2(RG)
NetR87_2: R87.2 R90.1 R94.1 R95.2
NetR93_1: R93.1 U24.12(CLKIN_N)
NetR96_2: R96.2 U24.6(LDO_IN)
NetR97_1: R97.1 U24.11(DOUT)
NetR98_1: R98.1 U24.10(DOUT_N)
NetR99_2: R99.2 R103.1
NetR100_2: R100.2 R101.1 R104.1 R111.1
NetR102_1: R102.1 R109.1 U25.7(OUT)
NetR106_1: R106.1 U25.3(RG)
NetR106_2: R106.2 U25.2(RG)
NetR111_2: R111.2 R114.1 R118.1 R119.2
NetR117_1: R117.1 U27.12(CLKIN_N)
NetR120_2: R120.2 U27.6(LDO_IN)
NetR121_1: R121.1 U27.11(DOUT)
NetR122_1: R122.1 U27.10(DOUT_N)

Not connected (* = marked no-connect by the designer): U21 1(NC) 4(NC) 5(NC) 15(NC); U24 1(NC) 4(NC) 5(NC) 15(NC); U27 1(NC) 4(NC) 5(NC) 15(NC)

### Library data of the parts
C110 C111 C115 C116 C118-C123 C127 C128 C130-C135 C139 C140 C142-C145 = C0603C104K5RACTU: as C5 on sheet Current Sense
C112 C124 C136 = 06033C104JAT2A: as C3 on sheet Current Sense
C113 C117 C125 C129 C137 C141 = 06031C472KAT2A: CAP, CERM, 4700pF, 100V, +/-10%, X7R, 0603; Manufacturer: AVX; Polarized: N; CompType: Capacitor; U/M: EA; Cap_F: 0.0000000047; Tolerance_%: 10; ESR_Ohm: 0.136; Value1: 0.136 ohm; VDC_V: 100; TaMin_C: -55; TaMax_C: 125
C114 C126 C138 = C1608C0G1E392J: as C4 on sheet Current Sense
D35-D40 = BAV99WT1G: as D3 on sheet Current Sense
J20-J22 = JUMPER_2X100MIL: as J3 on sheet Current Sense
R51 R52 R55 R70 R75 R76 R79 R94 R99 R100 R103 R118 = RES_KTR25JZPF2204: as R17 on sheet Current Sense
R53 R71 R77 R95 R101 R119 = RC0603FR-0747KL: RES 15.0K OHM 1/10W .1% SMD 0603; PartNumber: RT0603BRD0715KL-ND; Manufacturer: Yageo America; CompType: Resistor; Res_ohm: 15000; Value_Code: 15k0; Tolerance_%: 1; Power_W: 0.1; Value2: 0.1W; VDC_V: 150; TempCo: 25ppm/C; U/M: EA
R54 R57 R59 R60 R63 R65 R67 R69 R72 R78 R81 R83-R85 R89 R91 R93 R96 R102 R105 R107-R109 R113 R115 R117 R120 = CRCW06030000Z0EA: as R5 on sheet Current Sense
R56 R66 R80 R90 R104 R114 = RC0603FR-0756RL: RES, 56.0 ohm, 1%, 0.1W, 0603; Manufacturer: Yageo America; CompType: Resistor; Res_ohm: 56; Value_Code: 56R0; Tolerance_%: 1; Power_W: 0.1; VDC_V: 150; TempCo: 200 ppm/C; U/M: EA
R58 R82 R106 = RC0603FR-071KL: RES, 1.00k ohm, 1%, 0.1W, 0603; Manufacturer: Yageo America; CompType: Resistor; Res_ohm: 1000; Value_Code: 1k00; Tolerance_%: 1; Power_W: 0.1; VDC_V: 150; TempCo: 200 ppm/C; EIA_Code: E96; U/M: EA
R61 R68 R87 R92 R111 R116 = RES_KTR25JZPF2001: as R21 on sheet Current Sense
R62 R64 R86 R88 R110 R112 = RC0603FR-074K7L: RES, 4.70k ohm, 1%, 0.1W, 0603; Manufacturer: Yageo America; CompType: Resistor; Res_ohm: 4700; Value_Code: 4k70; Tolerance_%: 1; Power_W: 0.1; VDC_V: 150; TempCo: 200 ppm/C; U/M: EA
R73 R74 R97 R98 R121 R122 = CRCW060310R0FKEA: as R7 on sheet Current Sense
TP10-TP12 = TP-040_RND: as TP1 on sheet Current Sense
U19 U22 U25 = INA826IADGK: IC, Precision, 200uA, 36V Supply Instrument Amplifier.; Manufacturer: TI; Alternate Manufacturer: None; Area: 35250
U20 U23 U26 = OPA211AID: IC, 1.1nV/vHz Noise, Low Power, Precision OpAmp; Manufacturer: TI; Alternate Manufacturer: None; Area: 75900
U21 U24 U27 = AMC1304L25: as U1 on sheet Current Sense

## Sheet Power supply 1.SchDoc: Power Supply1
size 431 x 279 mm; Date: Not shown in title block; ApprovedBy: Not shown in title block; CheckedBy: Not shown in title block; Author: Not shown in title block; CompanyName: Not shown in title block; Engineer: Not shown in title block; Organization: Not shown in title block; Address1: Not shown in title block; Address2: Not shown in title block; Address3: Not shown in title block; Address4: Not shown in title block; DocumentNumber: 5; Revision: Use project parameter SCH_Rev; SheetNumber: 5; SheetTotal: 7; PageSetup: Record=PageOptions|CenterHorizontal=True|CenterVertical=True|PrintScale=0.62|XCorrection=1.00|YCorrection=1.00|PrintKind=0|BorderSize=5000000|LeftOffset=0|BottomOffset=0|Orientation=2|PaperLength=1000|PaperWidth=1000|Scale=100|PaperSource=15|PrintQuality=600|MediaType=1|DitherType=10|PaperKind=Letter|PrintScaleMode=1
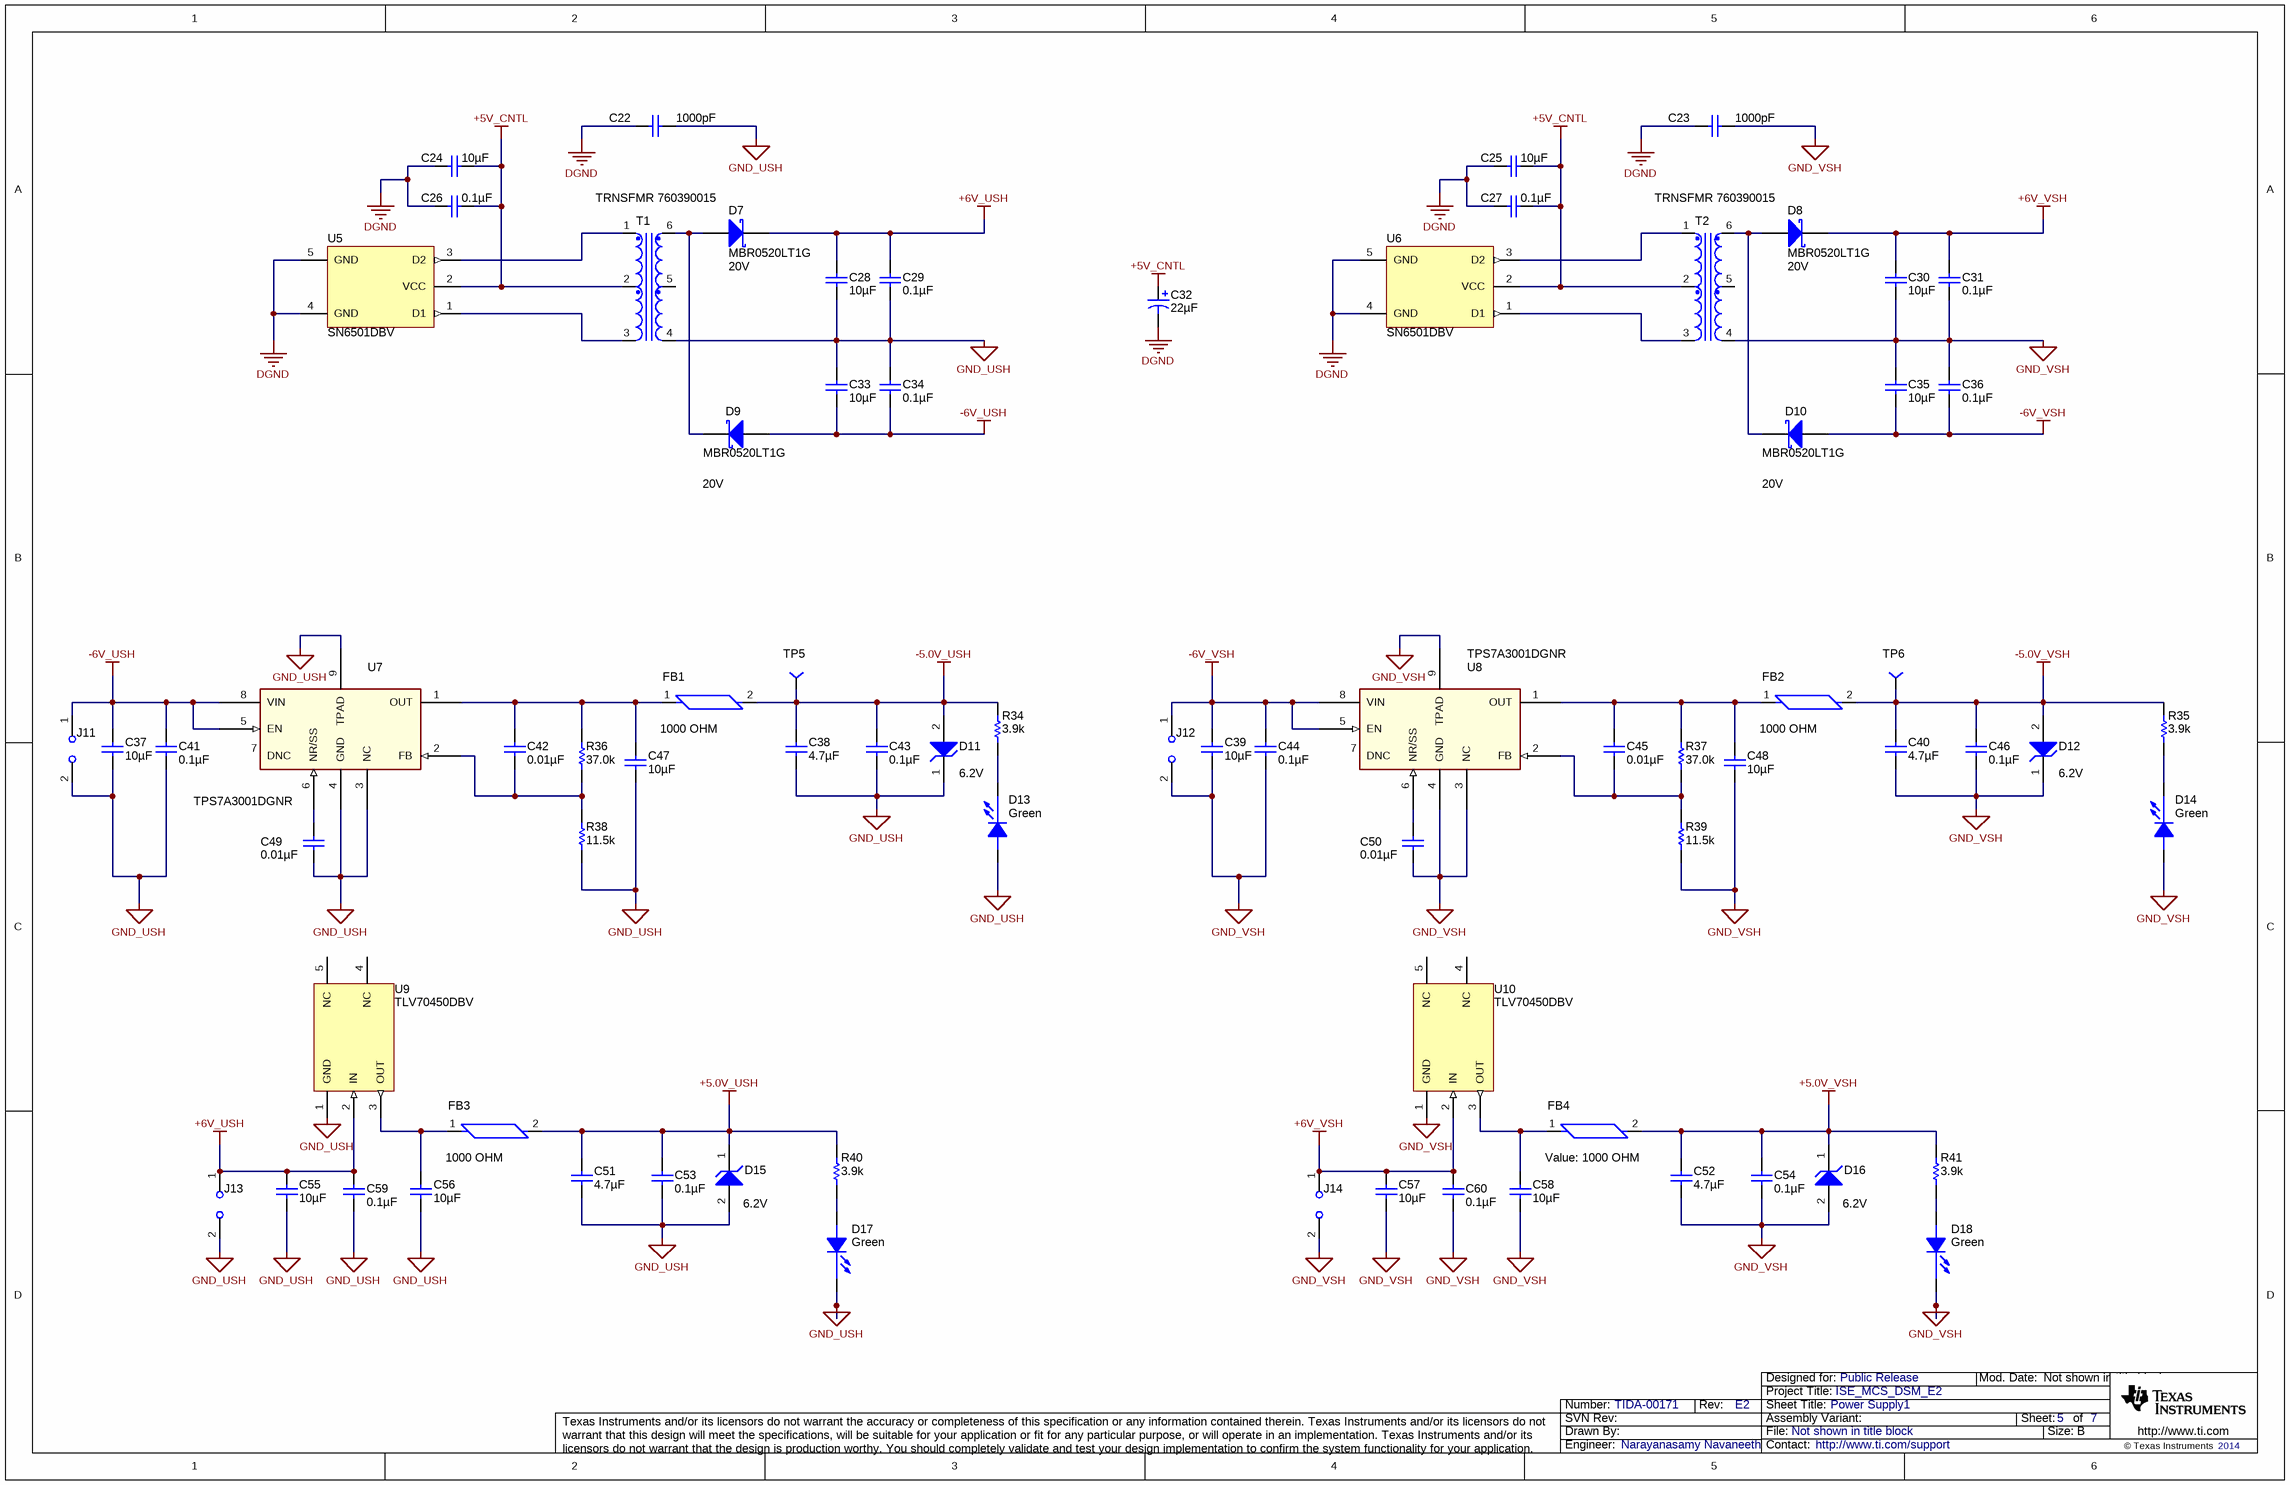
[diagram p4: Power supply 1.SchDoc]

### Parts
C22  value 1000pF  [1206]
C23  value 1000pF  [1206]
C24  ValueDisplayed: 10µF  [1210]
C25  ValueDisplayed: 10µF  [1210]
C26  ValueDisplayed: 0.1µF  [0603]
C27  ValueDisplayed: 0.1µF  [0603]
C28  ValueDisplayed: 10µF  [1210]
C29  ValueDisplayed: 0.1µF  [0603]
C30  ValueDisplayed: 10µF  [1210]
C31  ValueDisplayed: 0.1µF  [0603]
C32  ValueDisplayed: 22µF  [SM_RADIAL_5MM]  (hidden comment: UUD1E220MCL1GS)
C33  ValueDisplayed: 10µF  [1210]
C34  ValueDisplayed: 0.1µF  [0603]
C35  ValueDisplayed: 10µF  [1210]
C36  ValueDisplayed: 0.1µF  [0603]
C37  ValueDisplayed: 10µF  [1210]
C38  ValueDisplayed: 4.7µF  [0805_HV]
C39  ValueDisplayed: 10µF  [1210]
C40  ValueDisplayed: 4.7µF  [0805_HV]
C41  ValueDisplayed: 0.1µF  [0603]
C42  ValueDisplayed: 0.01µF  [0603]
C43  ValueDisplayed: 0.1µF  [0603]
C44  ValueDisplayed: 0.1µF  [0603]
C45  ValueDisplayed: 0.01µF  [0603]
C46  ValueDisplayed: 0.1µF  [0603]
C47  ValueDisplayed: 10µF  [1210]
C48  ValueDisplayed: 10µF  [1210]
C49  ValueDisplayed: 0.01µF  [0603]
C50  ValueDisplayed: 0.01µF  [0603]
C51  ValueDisplayed: 4.7µF  [0805_HV]
C52  ValueDisplayed: 4.7µF  [0805_HV]
C53  ValueDisplayed: 0.1µF  [0603]
C54  ValueDisplayed: 0.1µF  [0603]
C55  ValueDisplayed: 10µF  [1210]
C56  ValueDisplayed: 10µF  [1210]
C57  ValueDisplayed: 10µF  [1210]
C58  ValueDisplayed: 10µF  [1210]
C59  ValueDisplayed: 0.1µF  [0603]
C60  ValueDisplayed: 0.1µF  [0603]
D7  MBR0520LT1G  value 20V  [SOD-123]
D8  MBR0520LT1G  value 20V  [SOD-123]
D9  MBR0520LT1G  value 20V  [SOD-123]
D10  MBR0520LT1G  value 20V  [SOD-123]
D11  value 6.2V  [powerDI123]
D12  value 6.2V  [powerDI123]
D13  value Green  [LED0603AA]
D14  value Green  [LED0603AA]
D15  value 6.2V  [powerDI123]
D16  value 6.2V  [powerDI123]
D17  value Green  [LED0603AA]
D18  value Green  [LED0603AA]
FB1  value 1000 OHM  [FB0603]
FB2  value 1000 OHM  [FB0603]
FB3  value 1000 OHM  [FB0603]
FB4  value 1000 OHM  [FB0603]
J11  (no value)  [HDR100_1X2]
J12  (no value)  [HDR100_1X2]
J13  (no value)  [HDR100_1X2]
J14  (no value)  [HDR100_1X2]
R34  value 3.9k  [0603]
R35  value 3.9k  [0603]
R36  value 37.0k  [0603]
R37  value 37.0k  [0603]
R38  value 11.5k  [0603]
R39  value 11.5k  [0603]
R40  value 3.9k  [0603]
R41  value 3.9k  [0603]
T1  TRNSFMR 760390015  [760390015]
T2  TRNSFMR 760390015  [760390015]
TP5  (no value)  [TP-040_RND]
TP6  (no value)  [TP-040_RND]
U5  SN6501DBV  [DBV0005A_N]
U6  SN6501DBV  [DBV0005A_N]
U7  TPS7A3001DGNR  [MSOP8(DGN)]
U8  (no value)  [MSOP8(DGN)]
U9  TLV70450DBV  [DBV0005A_N]
U10  TLV70450DBV  [DBV0005A_N]

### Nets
+5.0V_USH: C51.2 C53.1 D15.1(K) FB3.2 R40.2
+5.0V_VSH: C52.2 C54.1 D16.1(K) FB4.2 R41.2
+5V_CNTL: C24.2 C25.2 C26.2 C27.2 C32.1(+) T1.2 T2.2 U5.2(VCC) U6.2(VCC)
+6V_USH: C28.1 C29.1 C55.2 C59.1 D7.1(K) J13.1 U9.2(IN)
+6V_VSH: C30.1 C31.1 C57.2 C60.1 D8.1(K) J14.1 U10.2(IN)
-5.0V_USH: C38.2 C43.1 D11.2(A) FB1.2 R34.2 TP5.1
-5.0V_VSH: C40.2 C46.1 D12.2(A) FB2.2 R35.2 TP6.1
-6V_USH: C33.2 C34.2 C37.2 C41.1 D9.2(A) J11.1 U7.5(EN) U7.8(VIN)
-6V_VSH: C35.2 C36.2 C39.2 C44.1 D10.2(A) J12.1 U8.5(EN) U8.8(VIN)
DGND: C22.1 C23.1 C24.1 C25.1 C26.1 C27.1 C32.2(-) U5.4(GND) U5.5(GND) U6.4(GND) U6.5(GND)
GND_USH: C22.2 C28.2 C29.2 C33.1 C34.1 C37.1 C38.1 C41.2 C43.2 C47.1 C49.1 C51.1 C53.2 C55.1 C56.1 C59.2 D11.1(K) D13.2(A) D15.2(A) D17.1(C) J11.2 J13.2 R38.1 T1.4 U7.3(NC) U7.4(GND) U7.9(TPAD) U9.1(GND)
GND_VSH: C23.2 C30.2 C31.2 C35.1 C36.1 C39.1 C40.1 C44.2 C46.2 C48.1 C50.1 C52.1 C54.2 C57.1 C58.1 C60.2 D12.1(K) D14.2(A) D16.2(A) D18.1(C) J12.2 J14.2 R39.1 T2.4 U8.3(NC) U8.4(GND) U8.9(TPAD) U10.1(GND)
NetC42_1: C42.1 R36.1 R38.2 U7.2(FB)
NetC42_2: C42.2 C47.2 FB1.1 R36.2 U7.1(OUT)
NetC45_1: C45.1 R37.1 R39.2 U8.2(FB)
NetC45_2: C45.2 C48.2 FB2.1 R37.2 U8.1(OUT)
NetC49_2: C49.2 U7.6(NR/SS)
NetC50_2: C50.2 U8.6(NR/SS)
NetC56_2: C56.2 FB3.1 U9.3(OUT)
NetC58_2: C58.2 FB4.1 U10.3(OUT)
NetD7_2: D7.2(A) D9.1(K) T1.6
NetD8_2: D8.2(A) D10.1(K) T2.6
NetD13_1: D13.1(C) R34.1
NetD14_1: D14.1(C) R35.1
NetD17_2: D17.2(A) R40.1
NetD18_2: D18.2(A) R41.1
NetT1_1: T1.1 U5.3(D2)
NetT1_3: T1.3 U5.1(D1)
NetT2_1: T2.1 U6.3(D2)
NetT2_3: T2.3 U6.1(D1)

Not connected (* = marked no-connect by the designer): T1 5; T2 5; U7 7(DNC); U8 7(DNC); U9 4(NC) 5(NC); U10 4(NC) 5(NC)

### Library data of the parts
C22 C23 = 202R18W102KV4E: CAP, CERM, 1000pF, 2KV 10% X7R 1206; Manufacturer: Johanson Dielectrics Inc; Polarized: N; CompType: Capacitor; Cap_F: 0.000000001; Tolerance_%: 0
C24 C25 C28 C30 C33 C35 C37 C39 C47 C48 C55-C58 = GMK325AB7106MM-T: CAP, CERM, 10uF, 35V, +/-20%, X7R, 1210; Manufacturer: Taiyo Yuden; Polarized: N; CompType: Capacitor; U/M: EA; Cap_F: 0.00001; Tolerance_%: 20; Value1: Unknown; VDC_V: 35; TaMin_C: -55; TaMax_C: 125
C26 C27 C29 C31 C34 C36 C41 C43 C44 C46 C53 C54 C59 C60 = C0603C104K5RACTU: as C5 on sheet Current Sense
C32 = UUD1E220MCL1GS: as C1 on sheet Current Sense
C38 C40 C51 C52 = C2012X5R1H475K125AB: CAP, CERM, 4.7uF, 50V, +/-10%, X5R, 0805; Manufacturer: TDK; Polarized: N; CompType: Capacitor; U/M: EA; Cap_F: 0.0000047; Tolerance_%: 10; Value1: Unknown; VDC_V: 50; TaMin_C: -55; TaMax_C: 85; Cap_Case: 0805
C42 C45 C49 C50 = 06031C103JAT2A: CAP, CERM, 0.01uF, 100V, +/-5%, X7R, 0603; Manufacturer: AVX; Polarized: N; CompType: Capacitor; U/M: EA; Cap_F: 0.00000001; Tolerance_%: 5; ESR_Ohm: 0.098; Value1: 0.098 ohm; VDC_V: 100; TaMin_C: -55; TaMax_C: 125
D7-D10 = MBR0520LT1G: Diode, Schottky, 20V, 0.5A, SOD-123; Manufacturer: ON Semiconductor; U/M: EA; Vf_V: 0.385; Value2: 0.385V; Io_A: 0.5; Vr_V: 20; TJmax_C: 125; RJC_CperW: 150
D11 D12 D15 D16 = DFLZ6V2-7: Diode, Zener, 6.2V, 1W, PowerDI123; Manufacturer: Diodes Inc.; U/M: EA; Power_W: 1; Vz_V: 6.2; RJA_CperW: 110
D13 D14 D17 D18 = LED_LG L29K-G2J1-24-Z: LED SmartLED Green 570NM; Manufacturer: OSRAM; SymbolCreator: x0120606
FB1-FB4 = MMZ1608B102C: FERRITE CHIP 1000 OHM 300MA 0603; Manufacturer: TDK Corporation; CompType: Ferrite Bead
J11-J14 = JUMPER_2X100MIL: as J3 on sheet Current Sense
R34 R35 R40 R41 = CRCW06033K90JNEA: RES, 3.9k ohm, 5%, 0.1W, 0603; Manufacturer: Vishay-Dale; CompType: Resistor; Res_ohm: 3900; Value_Code: 3k90; Tolerance_%: 5; Power_W: 0.1; VDC_V: 75; TempCo: 200 ppm/C; EIA_Code: E24; U/M: EA
R36 R37 = RT0603BRD0737KL: RES, 37.0k ohm, 0.1%, 0.1W, 0603; Manufacturer: Yageo America; CompType: Resistor; Res_ohm: 37000; Value_Code: 37k0; Tolerance_%: 0.1; VDC_V: 75; TempCo: 25 ppm/C; EIA_Code: E192; U/M: EA
R38 R39 = CRCW060311K5FKEA: RES, 11.5k ohm, 1%, 0.1W, 0603; Manufacturer: Vishay-Dale; CompType: Resistor; Res_ohm: 11500; Value_Code: 11k5; Tolerance_%: 1; Power_W: 0.1; VDC_V: 75; TempCo: 100 ppm/C; EIA_Code: E96; U/M: EA
T1 T2 = TRNSFMR 760390015: Transformer 475uH SMD; PartNumber: 750342271; Manufacturer: Wurth Electronics Midcom
TP5 TP6 = TP-040_RND: as TP1 on sheet Current Sense
U5 U6 = SN6501DBV: Transformer Driver for Isolated Power Supplies, DBV0005A; Alternate Manufacturer: None; Manufacturer: Texas Instruments; SymbolCreator: a0411947; CompType: IC; U/M: EA
U7 U8 = TPS7A3001DGNR: -36V, -200mA, Ultralow-Noise, Negative Linear Regulator; Alternate Manufacturer: None; Manufacturer: Texas Instruments; CompType: IC; SymbolCreator: x0120606
U9 U10 = TLV70450DBV: Regulator, LDO, 5V, 0.15A, SOT23-5; Alternate Manufacturer: None; Manufacturer: Texas Instruments; SymbolCreator: x0120606; CompType: IC

## Sheet Power supply 2.SchDoc: Power Supply2
size 431 x 279 mm; Date: Not shown in title block; ApprovedBy: Not shown in title block; CheckedBy: Not shown in title block; Author: Not shown in title block; CompanyName: Not shown in title block; Engineer: Not shown in title block; Organization: Not shown in title block; Address1: Not shown in title block; Address2: Not shown in title block; Address3: Not shown in title block; Address4: Not shown in title block; DocumentNumber: 6; Revision: Use project parameter SCH_Rev; SheetNumber: 6; SheetTotal: 7; PageSetup: Record=PageOptions|CenterHorizontal=True|CenterVertical=True|PrintScale=1.00|XCorrection=1.00|YCorrection=1.00|PrintKind=0|BorderSize=5000000|LeftOffset=0|BottomOffset=0|Orientation=2|PaperLength=1000|PaperWidth=1000|Scale=100|PaperSource=15|PrintQuality=600|MediaType=1|DitherType=10|PaperKind=Letter|PrintScaleMode=1
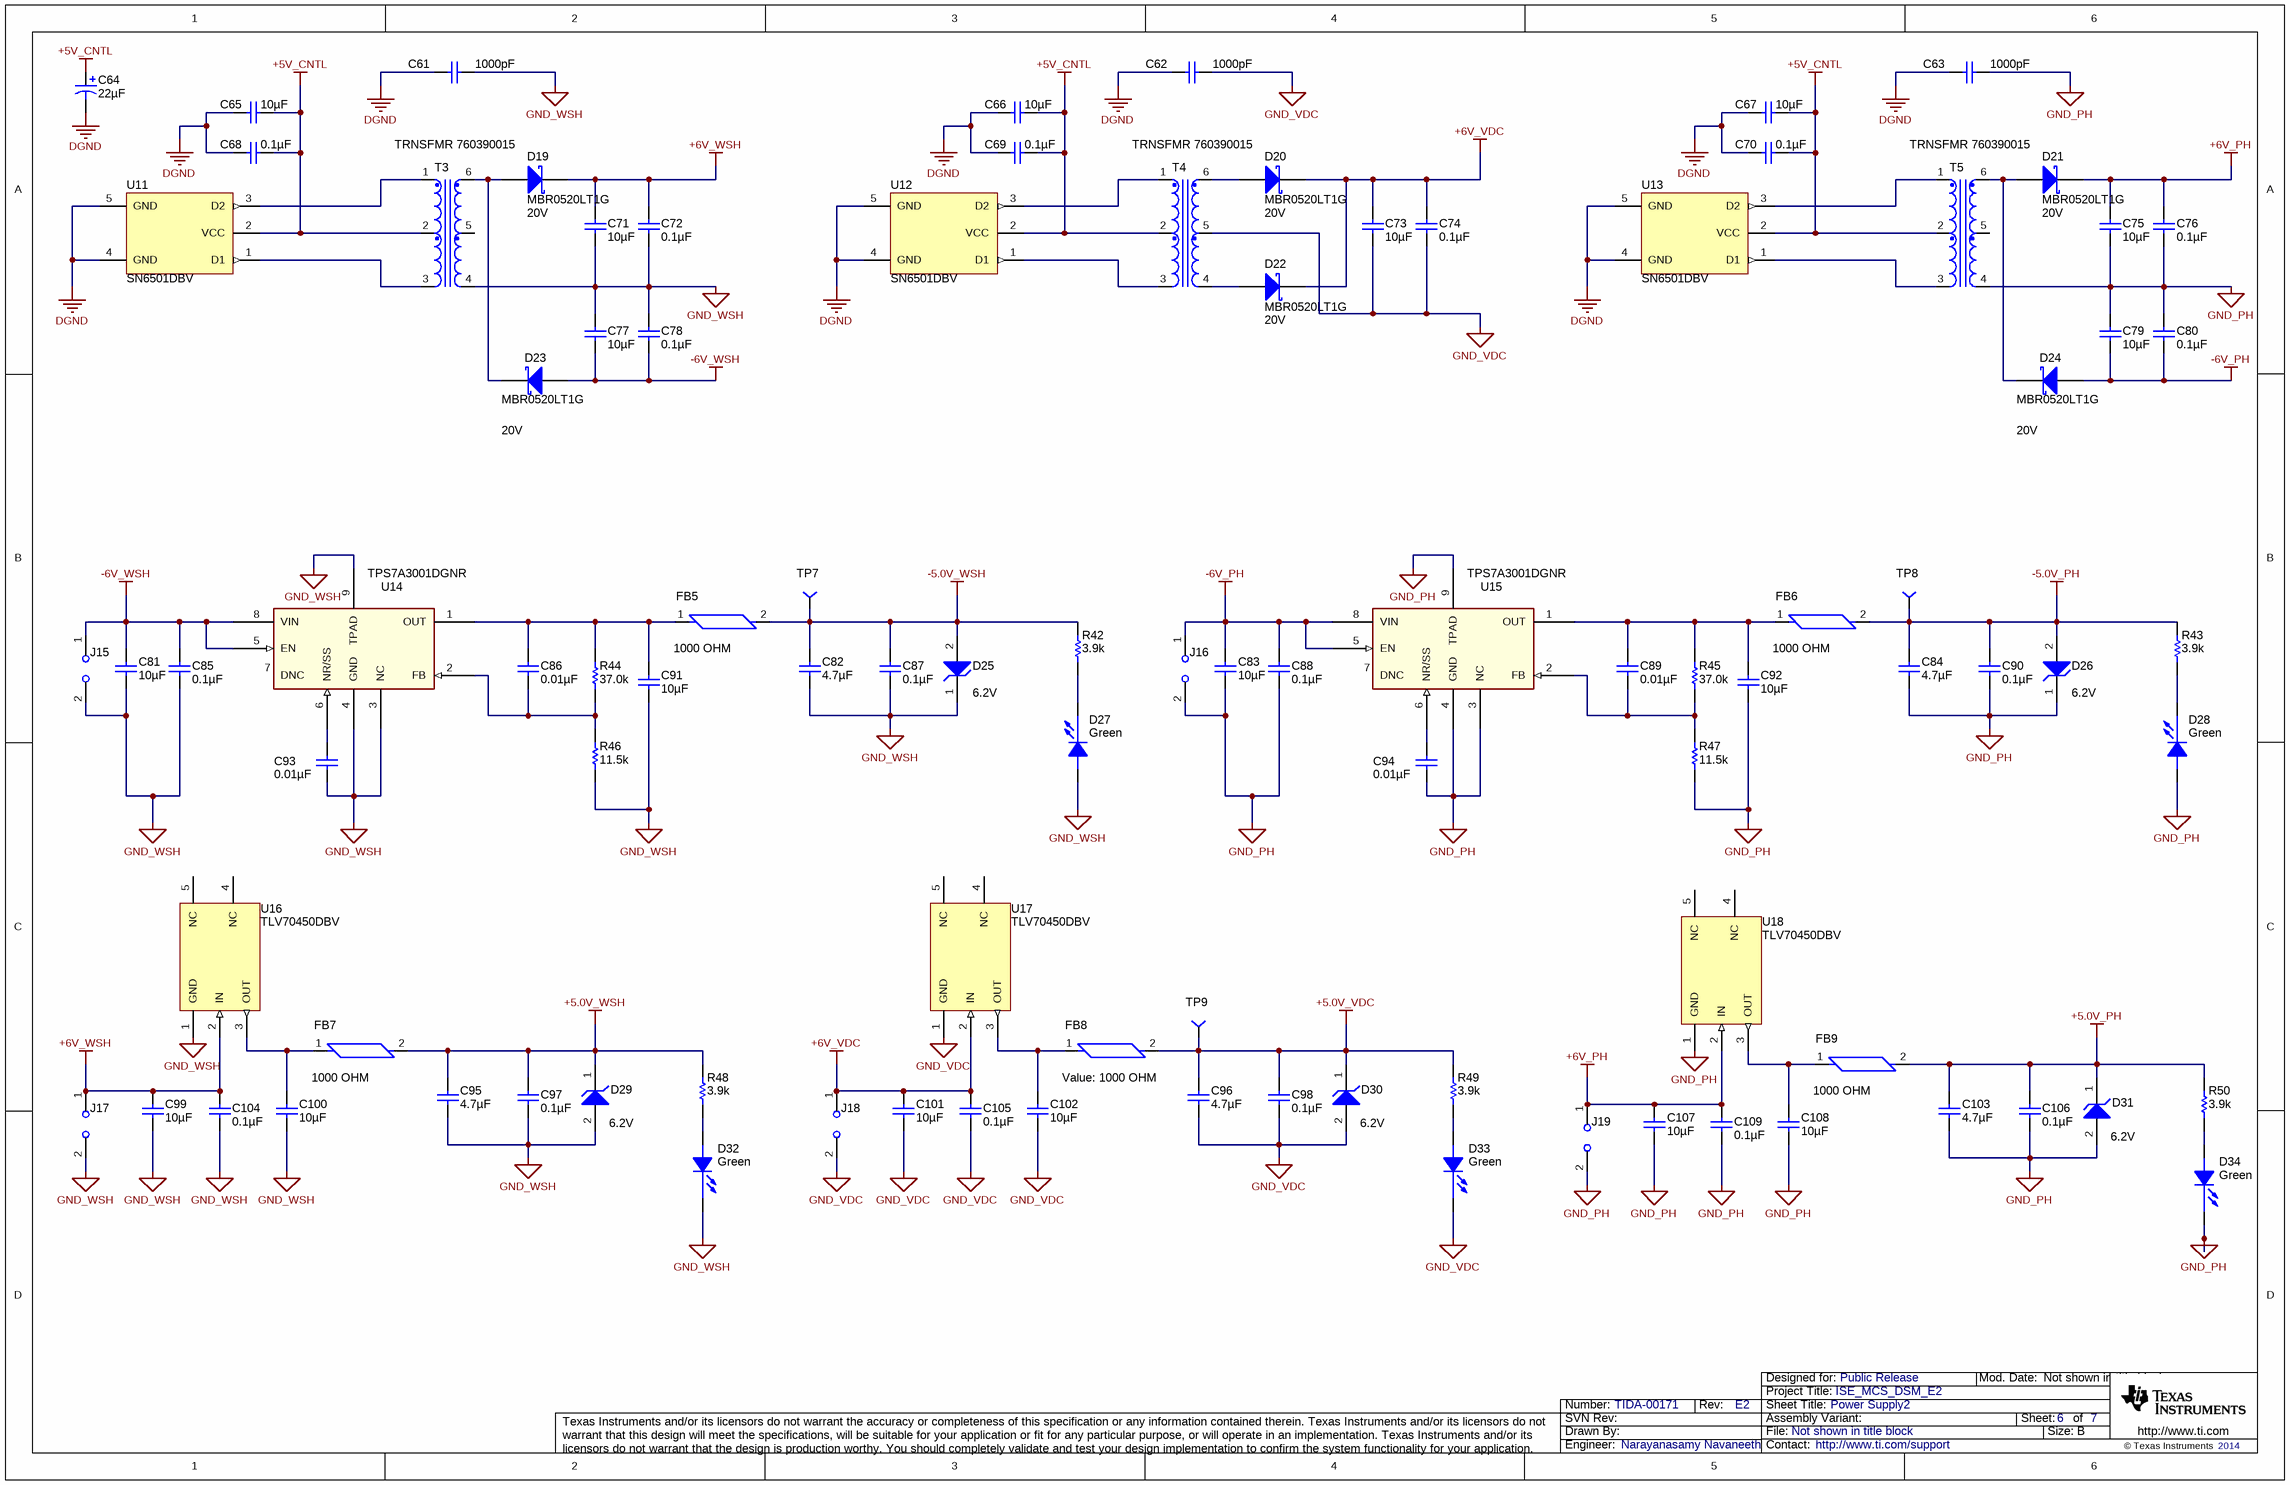
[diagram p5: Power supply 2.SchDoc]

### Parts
C61  value 1000pF  [1206]
C62  value 1000pF  [1206]
C63  value 1000pF  [1206]
C64  ValueDisplayed: 22µF  [SM_RADIAL_5MM]  (hidden comment: UUD1E220MCL1GS)
C65  ValueDisplayed: 10µF  [1210]
C66  ValueDisplayed: 10µF  [1210]
C67  ValueDisplayed: 10µF  [1210]
C68  ValueDisplayed: 0.1µF  [0603]
C69  ValueDisplayed: 0.1µF  [0603]
C70  ValueDisplayed: 0.1µF  [0603]
C71  ValueDisplayed: 10µF  [1210]
C72  ValueDisplayed: 0.1µF  [0603]
C73  ValueDisplayed: 10µF  [1210]
C74  ValueDisplayed: 0.1µF  [0603]
C75  ValueDisplayed: 10µF  [1210]
C76  ValueDisplayed: 0.1µF  [0603]
C77  ValueDisplayed: 10µF  [1210]
C78  ValueDisplayed: 0.1µF  [0603]
C79  ValueDisplayed: 10µF  [1210]
C80  ValueDisplayed: 0.1µF  [0603]
C81  ValueDisplayed: 10µF  [1210]
C82  ValueDisplayed: 4.7µF  [0805_HV]
C83  ValueDisplayed: 10µF  [1210]
C84  ValueDisplayed: 4.7µF  [0805_HV]
C85  ValueDisplayed: 0.1µF  [0603]
C86  ValueDisplayed: 0.01µF  [0603]
C87  ValueDisplayed: 0.1µF  [0603]
C88  ValueDisplayed: 0.1µF  [0603]
C89  ValueDisplayed: 0.01µF  [0603]
C90  ValueDisplayed: 0.1µF  [0603]
C91  ValueDisplayed: 10µF  [1210]
C92  ValueDisplayed: 10µF  [1210]
C93  ValueDisplayed: 0.01µF  [0603]
C94  ValueDisplayed: 0.01µF  [0603]
C95  ValueDisplayed: 4.7µF  [0805_HV]
C96  ValueDisplayed: 4.7µF  [0805_HV]
C97  ValueDisplayed: 0.1µF  [0603]
C98  ValueDisplayed: 0.1µF  [0603]
C99  ValueDisplayed: 10µF  [1210]
C100  ValueDisplayed: 10µF  [1210]
C101  ValueDisplayed: 10µF  [1210]
C102  ValueDisplayed: 10µF  [1210]
C103  ValueDisplayed: 4.7µF  [0805_HV]
C104  ValueDisplayed: 0.1µF  [0603]
C105  ValueDisplayed: 0.1µF  [0603]
C106  ValueDisplayed: 0.1µF  [0603]
C107  ValueDisplayed: 10µF  [1210]
C108  ValueDisplayed: 10µF  [1210]
C109  ValueDisplayed: 0.1µF  [0603]
D19  MBR0520LT1G  value 20V  [SOD-123]
D20  MBR0520LT1G  value 20V  [SOD-123]
D21  MBR0520LT1G  value 20V  [SOD-123]
D22  MBR0520LT1G  value 20V  [SOD-123]
D23  MBR0520LT1G  value 20V  [SOD-123]
D24  MBR0520LT1G  value 20V  [SOD-123]
D25  value 6.2V  [powerDI123]
D26  value 6.2V  [powerDI123]
D27  value Green  [LED0603AA]
D28  value Green  [LED0603AA]
D29  value 6.2V  [powerDI123]
D30  value 6.2V  [powerDI123]
D31  value 6.2V  [powerDI123]
D32  value Green  [LED0603AA]
D33  value Green  [LED0603AA]
D34  value Green  [LED0603AA]
FB5  value 1000 OHM  [FB0603]
FB6  value 1000 OHM  [FB0603]
FB7  value 1000 OHM  [FB0603]
FB8  value 1000 OHM  [FB0603]
FB9  value 1000 OHM  [FB0603]
J15  (no value)  [HDR100_1X2]
J16  (no value)  [HDR100_1X2]
J17  (no value)  [HDR100_1X2]
J18  (no value)  [HDR100_1X2]
J19  (no value)  [HDR100_1X2]
R42  value 3.9k  [0603]
R43  value 3.9k  [0603]
R44  value 37.0k  [0603]
R45  value 37.0k  [0603]
R46  value 11.5k  [0603]
R47  value 11.5k  [0603]
R48  value 3.9k  [0603]
R49  value 3.9k  [0603]
R50  value 3.9k  [0603]
T3  TRNSFMR 760390015  [760390015]
T4  TRNSFMR 760390015  [760390015]
T5  TRNSFMR 760390015  [760390015]
TP7  (no value)  [TP-040_RND]
TP8  (no value)  [TP-040_RND]
TP9  (no value)  [TP-040_RND]
U11  SN6501DBV  [DBV0005A_N]
U12  SN6501DBV  [DBV0005A_N]
U13  SN6501DBV  [DBV0005A_N]
U14  (no value)  [MSOP8(DGN)]
U15  (no value)  [MSOP8(DGN)]
U16  TLV70450DBV  [DBV0005A_N]
U17  TLV70450DBV  [DBV0005A_N]
U18  TLV70450DBV  [DBV0005A_N]

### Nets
+5.0V_PH: C103.2 C106.1 D31.1(K) FB9.2 R50.2
+5.0V_VDC: C96.2 C98.1 D30.1(K) FB8.2 R49.2 TP9.1
+5.0V_WSH: C95.2 C97.1 D29.1(K) FB7.2 R48.2
+5V_CNTL: C64.1(+) C65.2 C66.2 C67.2 C68.2 C69.2 C70.2 T3.2 T4.2 T5.2 U11.2(VCC) U12.2(VCC) U13.2(VCC)
+6V_PH: C75.1 C76.1 C107.2 C109.1 D21.1(K) J19.1 U18.2(IN)
+6V_VDC: C73.1 C74.1 C101.2 C105.1 D20.1(K) D22.1(K) J18.1 U17.2(IN)
+6V_WSH: C71.1 C72.1 C99.2 C104.1 D19.1(K) J17.1 U16.2(IN)
-5.0V_PH: C84.2 C90.1 D26.2(A) FB6.2 R43.2 TP8.1
-5.0V_WSH: C82.2 C87.1 D25.2(A) FB5.2 R42.2 TP7.1
-6V_PH: C79.2 C80.2 C83.2 C88.1 D24.2(A) J16.1 U15.5(EN) U15.8(VIN)
-6V_WSH: C77.2 C78.2 C81.2 C85.1 D23.2(A) J15.1 U14.5(EN) U14.8(VIN)
DGND: C61.1 C62.1 C63.1 C64.2(-) C65.1 C66.1 C67.1 C68.1 C69.1 C70.1 U11.4(GND) U11.5(GND) U12.4(GND) U12.5(GND) U13.4(GND) U13.5(GND)
GND_PH: C63.2 C75.2 C76.2 C79.1 C80.1 C83.1 C84.1 C88.2 C90.2 C92.1 C94.1 C103.1 C106.2 C107.1 C108.1 C109.2 D26.1(K) D28.2(A) D31.2(A) D34.1(C) J16.2 J19.2 R47.1 T5.4 U15.3(NC) U15.4(GND) U15.9(TPAD) U18.1(GND)
GND_VDC: C62.2 C73.2 C74.2 C96.1 C98.2 C101.1 C102.1 C105.2 D30.2(A) D33.1(C) J18.2 T4.5 U17.1(GND)  [project net DCLINK_N]
GND_WSH: C61.2 C71.2 C72.2 C77.1 C78.1 C81.1 C82.1 C85.2 C87.2 C91.1 C93.1 C95.1 C97.2 C99.1 C100.1 C104.2 D25.1(K) D27.2(A) D29.2(A) D32.1(C) J15.2 J17.2 R46.1 T3.4 U14.3(NC) U14.4(GND) U14.9(TPAD) U16.1(GND)
NetC86_1: C86.1 R44.1 R46.2 U14.2(FB)
NetC86_2: C86.2 C91.2 FB5.1 R44.2 U14.1(OUT)
NetC89_1: C89.1 R45.1 R47.2 U15.2(FB)
NetC89_2: C89.2 C92.2 FB6.1 R45.2 U15.1(OUT)
NetC93_2: C93.2 U14.6(NR/SS)
NetC94_2: C94.2 U15.6(NR/SS)
NetC100_2: C100.2 FB7.1 U16.3(OUT)
NetC102_2: C102.2 FB8.1 U17.3(OUT)
NetC108_2: C108.2 FB9.1 U18.3(OUT)
NetD19_2: D19.2(A) D23.1(K) T3.6
NetD20_2: D20.2(A) T4.6
NetD21_2: D21.2(A) D24.1(K) T5.6
NetD22_2: D22.2(A) T4.4
NetD27_1: D27.1(C) R42.1
NetD28_1: D28.1(C) R43.1
NetD32_2: D32.2(A) R48.1
NetD33_2: D33.2(A) R49.1
NetD34_2: D34.2(A) R50.1
NetT3_1: T3.1 U11.3(D2)
NetT3_3: T3.3 U11.1(D1)
NetT4_1: T4.1 U12.3(D2)
NetT4_3: T4.3 U12.1(D1)
NetT5_1: T5.1 U13.3(D2)
NetT5_3: T5.3 U13.1(D1)

Not connected (* = marked no-connect by the designer): T3 5; T5 5; U14 7(DNC); U15 7(DNC); U16 4(NC) 5(NC); U17 4(NC) 5(NC); U18 4(NC) 5(NC)

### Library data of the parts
C61-C63 = 202R18W102KV4E: as C22 on sheet Power supply 1
C64 = UUD1E220MCL1GS: as C1 on sheet Current Sense
C65-C67 C71 C73 C75 C77 C79 C81 C83 C91 C92 C99-C102 C107 C108 = GMK325AB7106MM-T: as C24 on sheet Power supply 1
C68-C70 C72 C74 C76 C78 C80 C85 C87 C88 C90 C97 C98 C104-C106 C109 = C0603C104K5RACTU: as C5 on sheet Current Sense
C82 C84 C95 C96 C103 = C2012X5R1H475K125AB: as C38 on sheet Power supply 1
C86 C89 C93 C94 = 06031C103JAT2A: as C42 on sheet Power supply 1
D19-D24 = MBR0520LT1G: as D7 on sheet Power supply 1
D25 D26 D29-D31 = DFLZ6V2-7: as D11 on sheet Power supply 1
D27 D28 D32-D34 = LED_LG L29K-G2J1-24-Z: as D13 on sheet Power supply 1
FB5-FB9 = MMZ1608B102C: as FB1 on sheet Power supply 1
J15-J19 = JUMPER_2X100MIL: as J3 on sheet Current Sense
R42 R43 R48-R50 = CRCW06033K90JNEA: as R34 on sheet Power supply 1
R44 R45 = RT0603BRD0737KL: as R36 on sheet Power supply 1
R46 R47 = CRCW060311K5FKEA: as R38 on sheet Power supply 1
T3-T5 = TRNSFMR 760390015: as T1 on sheet Power supply 1
TP7-TP9 = TP-040_RND: as TP1 on sheet Current Sense
U11-U13 = SN6501DBV: as U5 on sheet Power supply 1
U14 U15 = TPS7A3001DGNR: as U7 on sheet Power supply 1
U16-U18 = TLV70450DBV: as U9 on sheet Power supply 1

## Sheet Hardware.SchDoc: Hardware - MIiscellaneous
size 431 x 279 mm; Date: Not shown in title block; ApprovedBy: Not shown in title block; CheckedBy: Not shown in title block; Author: Not shown in title block; CompanyName: Not shown in title block; Engineer: Not shown in title block; Organization: Not shown in title block; Address1: Not shown in title block; Address2: Not shown in title block; Address3: Not shown in title block; Address4: Not shown in title block; DocumentNumber: 7; Revision: Use project parameter SCH_Rev; SheetNumber: 7; SheetTotal: 7; PageSetup: Record=PageOptions|CenterHorizontal=True|CenterVertical=True|PrintScale=1.00|XCorrection=1.00|YCorrection=1.00|PrintKind=0|BorderSize=5000000|LeftOffset=0|BottomOffset=0|Orientation=2|PaperLength=1000|PaperWidth=1000|Scale=100|PaperSource=15|PrintQuality=600|MediaType=1|DitherType=10|PaperKind=Letter|PrintScaleMode=1
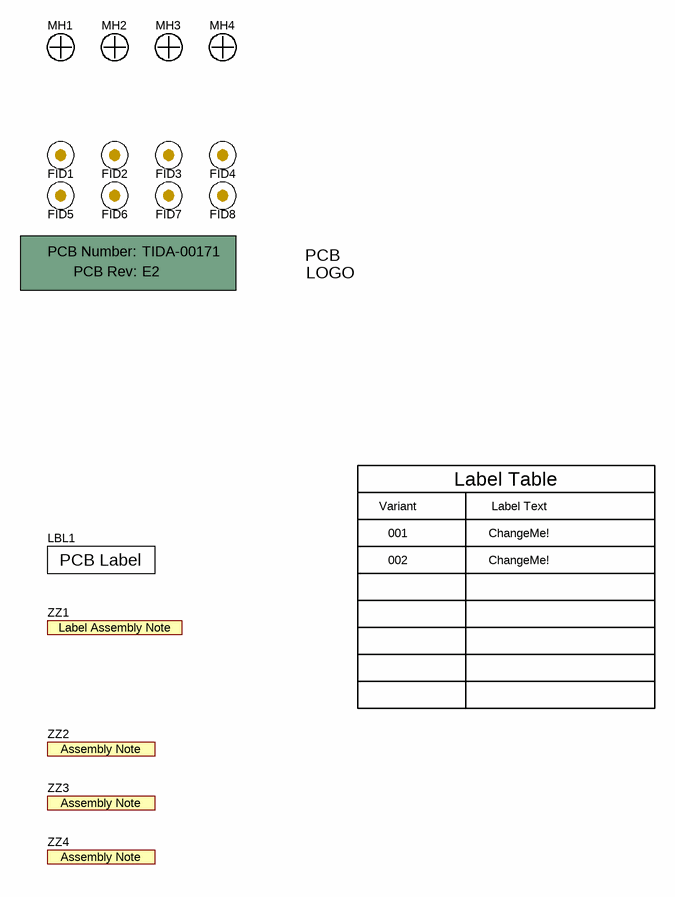
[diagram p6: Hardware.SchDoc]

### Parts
!PCB1  (no value)  (mechanical)
FID1  (no value)  [Fiducial10-20]
FID2  (no value)  [Fiducial10-20]
FID3  (no value)  [Fiducial10-20]
FID4  (no value)  [Fiducial10-20]
FID5  (no value)  [Fiducial10-20]
FID6  (no value)  [Fiducial10-20]
FID7  (no value)  [Fiducial10-20]
FID8  (no value)  [Fiducial10-20]
LBL1  (no value)  [Label_650x200]
Logo1  (no value)  [TI_Stacked_SolderMask_Small]  (no BOM)
MH1  (no value)  [MH3.2]
MH2  (no value)  [MH3.2]
MH3  (no value)  [MH3.2]
MH4  (no value)  [MH3.2]
ZZ1  (no value)  [AssemblyNoteLabel]  (no BOM)
ZZ2  (no value)  [AssemblyNote]  (no BOM)
ZZ3  (no value)  [AssemblyNote]  (no BOM)
ZZ4  (no value)  [AssemblyNote]  (no BOM)

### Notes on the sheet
- Variant
- Label Table
- Label Text
- 001
- 002
- ChangeMe!

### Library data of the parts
!PCB1 = PCB: Printed Circuit Board; Manufacturer: Any; PartNumber: TIDA-00171; SymbolCreator: a0412235
FID1-FID8 = Fiducial: Fiducial mark.  There is nothing to buy or mount.; SymbolCreator: codlsc
LBL1 = THT-14-423-10: Thermal Transfer Printable Labels, 0.650" W x 0.200" H - 10,000 per roll; Manufacturer: Brady; SymbolCreator: a0412235; CompType: Label; Note: Size: 0.65" x 0.20 "
Logo1 = TI_Logo: Texas Instrument Corporate Signature; SymbolCreator: codlsc
MH1-MH4 = NY PMS 440 0025 PH: Mountin hole, NPTH Drill 3.2mm; CompType: Hardware
ZZ1 = AssemblyNoteLabel: This Assembly Note is for PCB labels only; SymbolCreator: a0412235
ZZ2 = AssemblyNote: These assemblies are ESD sensitive, ESD precautions shall be observed.; SymbolCreator: codlsc
ZZ3 = AssemblyNote: These assemblies must be clean and free from flux and all contaminants. Use of no clean flux is not acceptable.; SymbolCreator: codlsc
ZZ4 = AssemblyNote: These assemblies must comply with workmanship standards IPC-A-610 Class 2, unless otherwise specified.; SymbolCreator: codlsc

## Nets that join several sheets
+3.3V_DVDD: Current Sense (16 pins), Voltage signal conditioning (9 pins)
+5.0V_PH: Voltage signal conditioning (27 pins), Power supply 2 (5 pins)
+5.0V_USH: Current Sense (5 pins), Power supply 1 (5 pins)
+5.0V_VDC: Current Sense (C19.1 J9.2 R26.1), Power supply 2 (6 pins)
+5.0V_VSH: Current Sense (5 pins), Power supply 1 (5 pins)
+5.0V_WSH: Current Sense (5 pins), Power supply 2 (5 pins)
+5V_CNTL: Current Sense (C2.1 C8.1 J1.3 J1.37), Power supply 1 (9 pins), Power supply 2 (13 pins)
-5.0V_PH: Voltage signal conditioning (18 pins), Power supply 2 (6 pins)
-5.0V_USH: Current Sense (D1.1 D2.1), Power supply 1 (6 pins)
-5.0V_VSH: Current Sense (D3.1 D4.1), Power supply 1 (6 pins)
-5.0V_WSH: Current Sense (D5.1 D6.1), Power supply 2 (6 pins)
DCLINK_N: Current Sense (8 pins), Power supply 2 (13 pins)
DGND: Current Sense (24 pins), Voltage signal conditioning (9 pins), Power supply 1 (11 pins), Power supply 2 (16 pins)
GND_PH: Current Sense (J7.1), Voltage signal conditioning (42 pins), Power supply 2 (28 pins)
GND_USH: Current Sense (7 pins), Voltage signal conditioning (R51.1 R52.1 R118.2), Power supply 1 (28 pins)
GND_VSH: Current Sense (7 pins), Voltage signal conditioning (R70.2 R75.1 R76.1), Power supply 1 (28 pins)
GND_WSH: Current Sense (7 pins), Voltage signal conditioning (R94.2 R99.1 R100.1), Power supply 2 (28 pins)
CLKN_U_PH: Current Sense (J1.22), Voltage signal conditioning (R69.2)
CLKN_V_PH: Current Sense (J1.26), Voltage signal conditioning (R93.2)
CLKN_W_PH: Current Sense (J1.30), Voltage signal conditioning (R117.2)
CLKP_U_PH: Current Sense (J1.21), Voltage signal conditioning (U21.13)
CLKP_V_PH: Current Sense (J1.25), Voltage signal conditioning (U24.13)
CLKP_W_PH: Current Sense (J1.29), Voltage signal conditioning (U27.13)
DOUTN_U_PH: Current Sense (J1.20), Voltage signal conditioning (R74.2)
DOUTN_V_PH: Current Sense (J1.24), Voltage signal conditioning (R98.2)
DOUTN_W_PH: Current Sense (J1.28), Voltage signal conditioning (R122.2)
DOUTP_U_PH: Current Sense (J1.19), Voltage signal conditioning (R73.2)
DOUTP_V_PH: Current Sense (J1.23), Voltage signal conditioning (R97.2)
DOUTP_W_PH: Current Sense (J1.27), Voltage signal conditioning (R121.2)

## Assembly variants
001: not fitted C14 C115 C127 C139 FID1 FID2 FID3 FID4 FID5 FID6 FID7 FID8 R2 R5 R8 R10 R13 R16 R23 R25 R28 R30 R33 R51 R54 R58 R59 R63 R67 R69 R74 R75 R78 R82 R83 R85 R91 R93 R98 R99 R102 R106 R107 R109 R115 R117 R122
